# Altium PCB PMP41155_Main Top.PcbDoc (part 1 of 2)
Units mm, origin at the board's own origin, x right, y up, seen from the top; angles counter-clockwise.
Board outline 74 x 151.7 mm, 8 copper layers (Top Layer, Signal Layer 1, Signal Layer 2, Signal Layer 3, Signal Layer 4, Signal Layer 5, Signal Layer 6, Bottom Layer), stack 1.534 mm thick; 14 components, 3 nets, 47 pads, 370 vias.
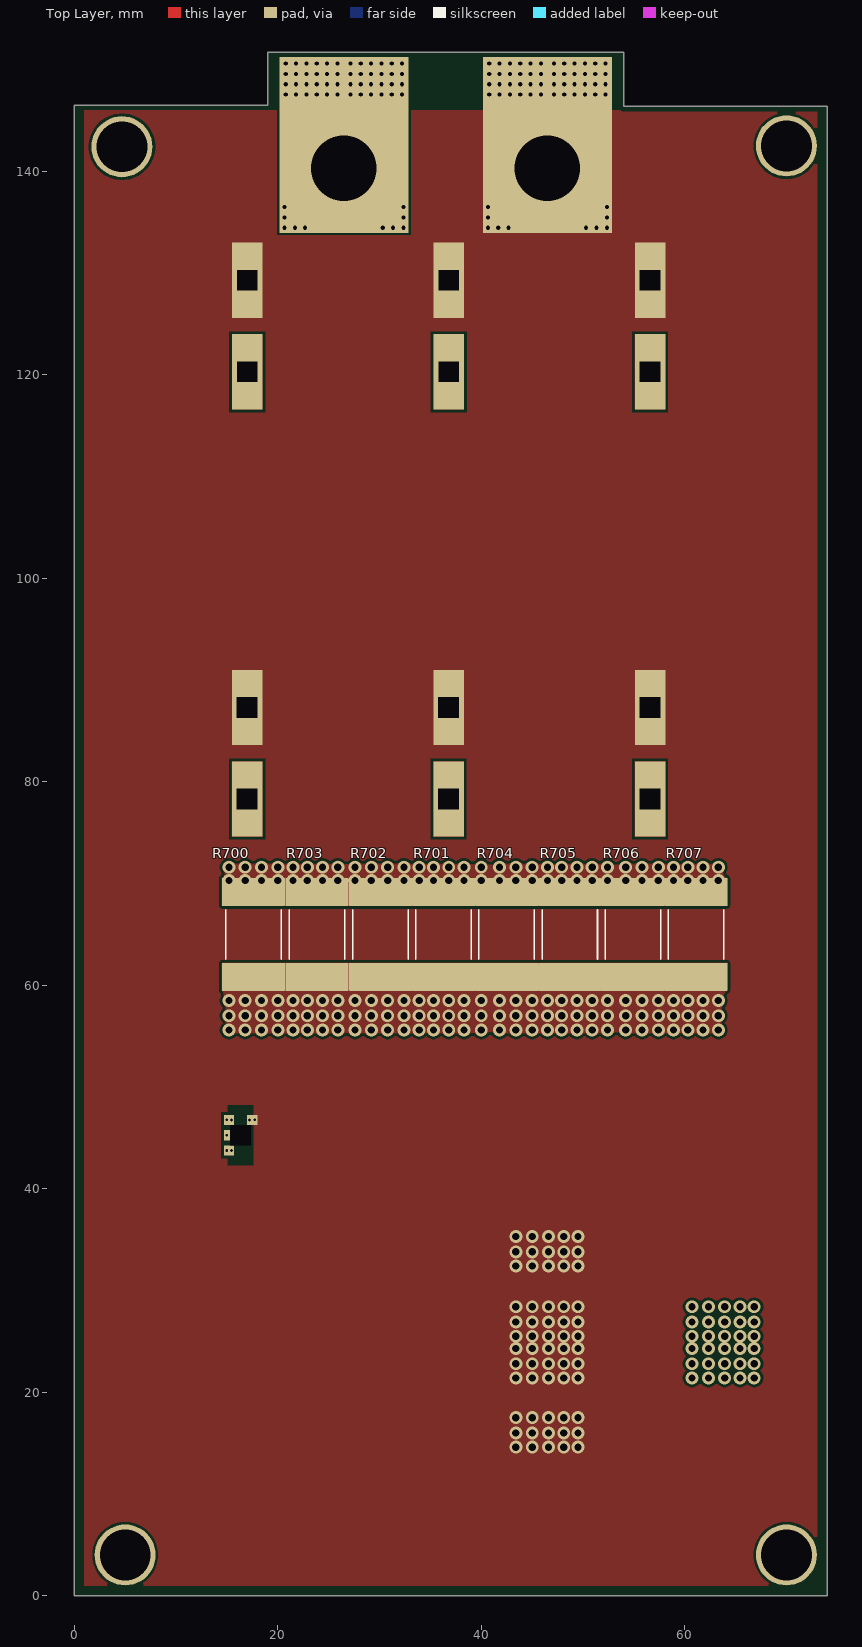
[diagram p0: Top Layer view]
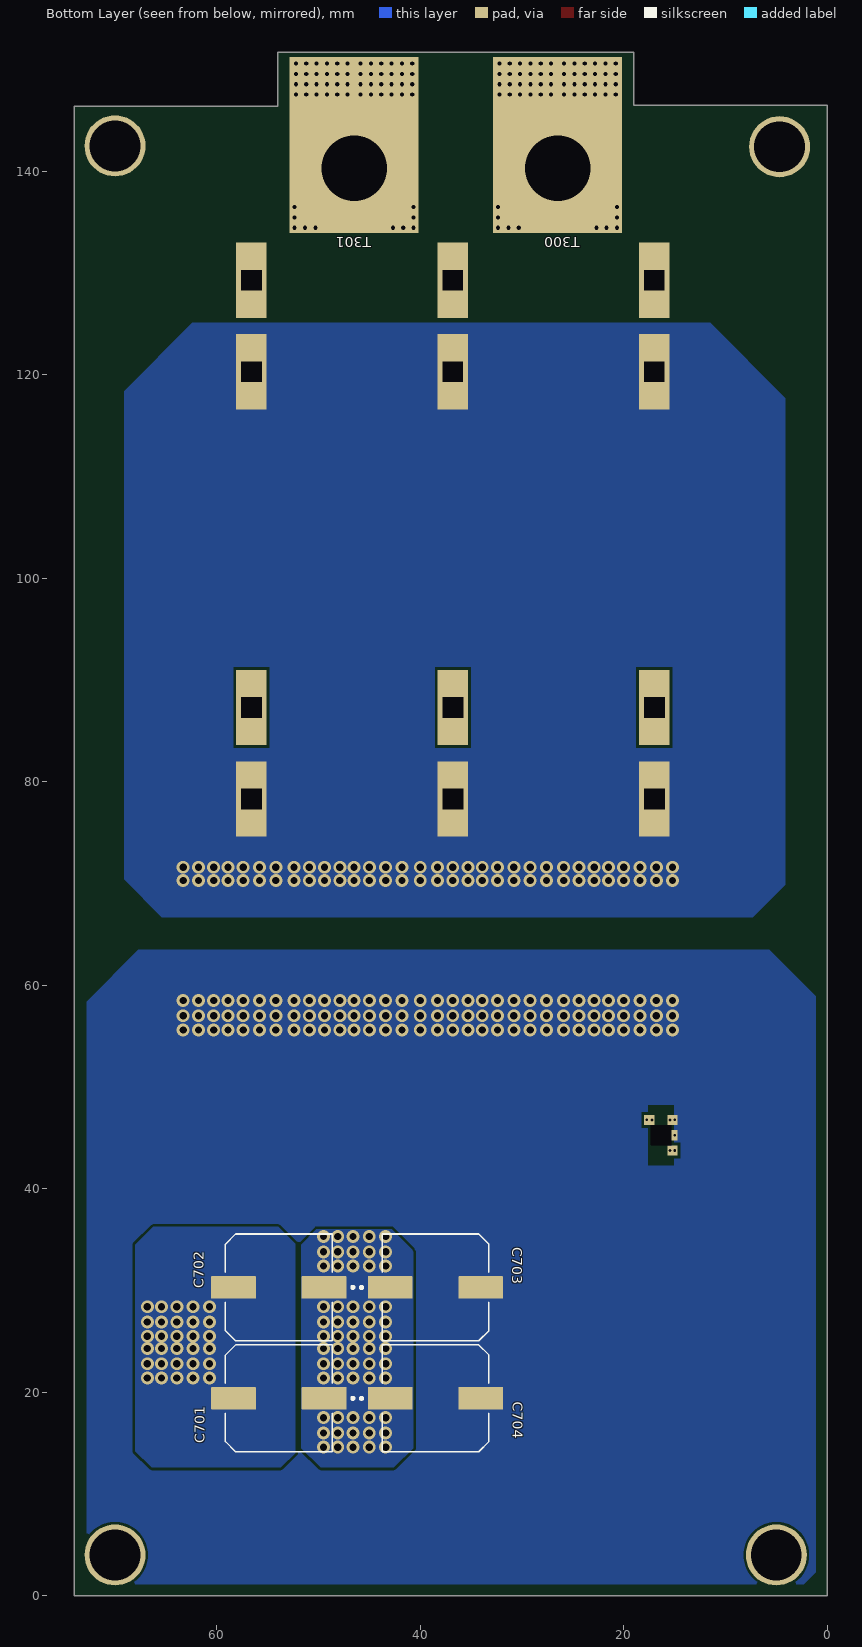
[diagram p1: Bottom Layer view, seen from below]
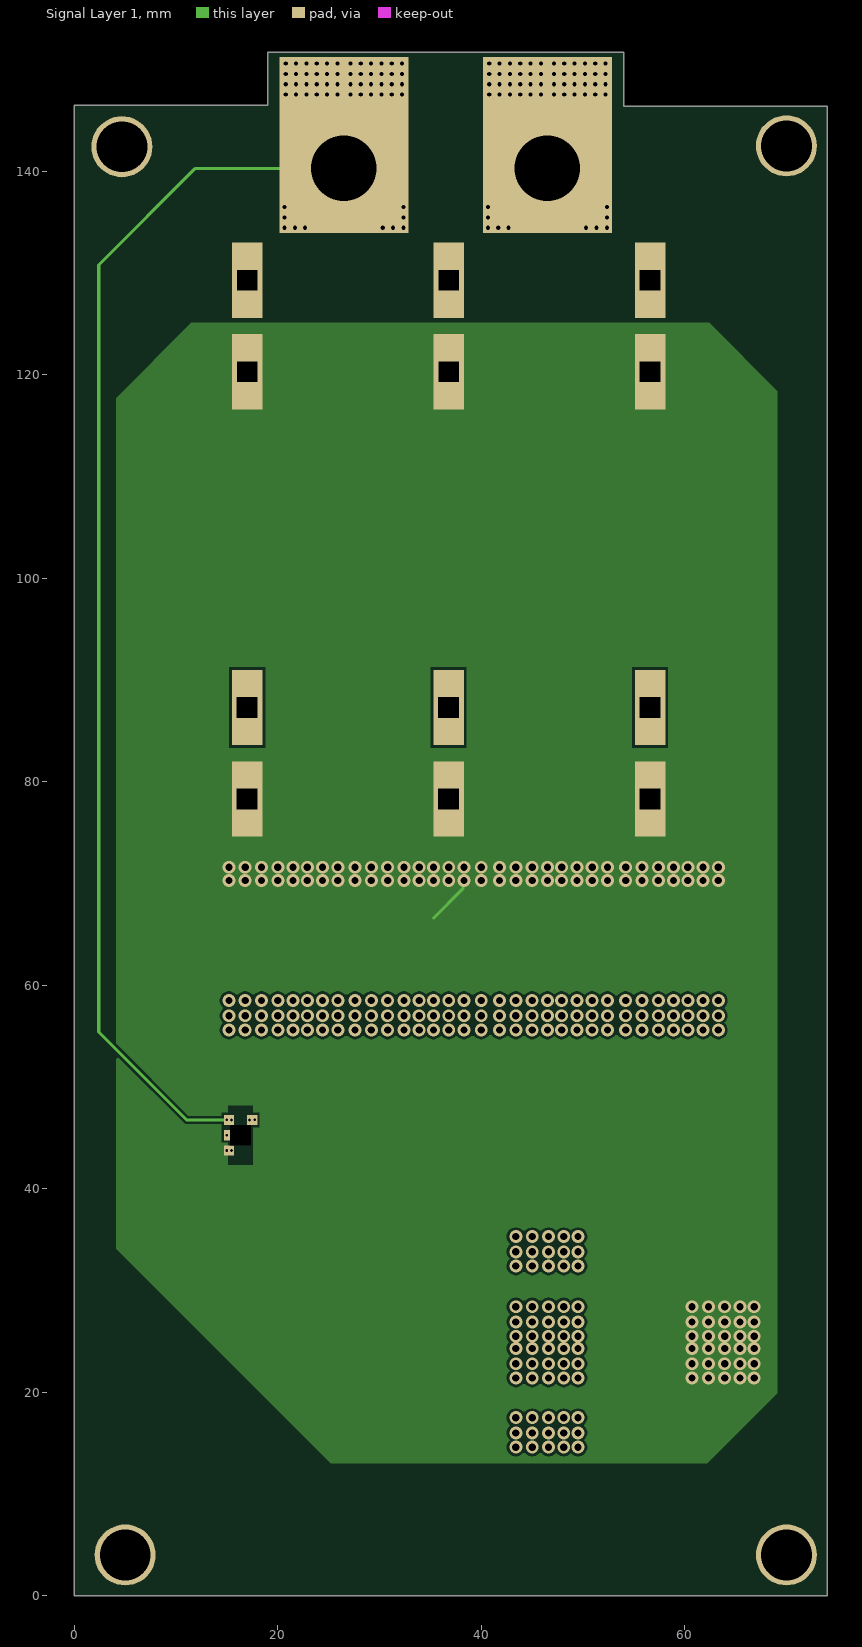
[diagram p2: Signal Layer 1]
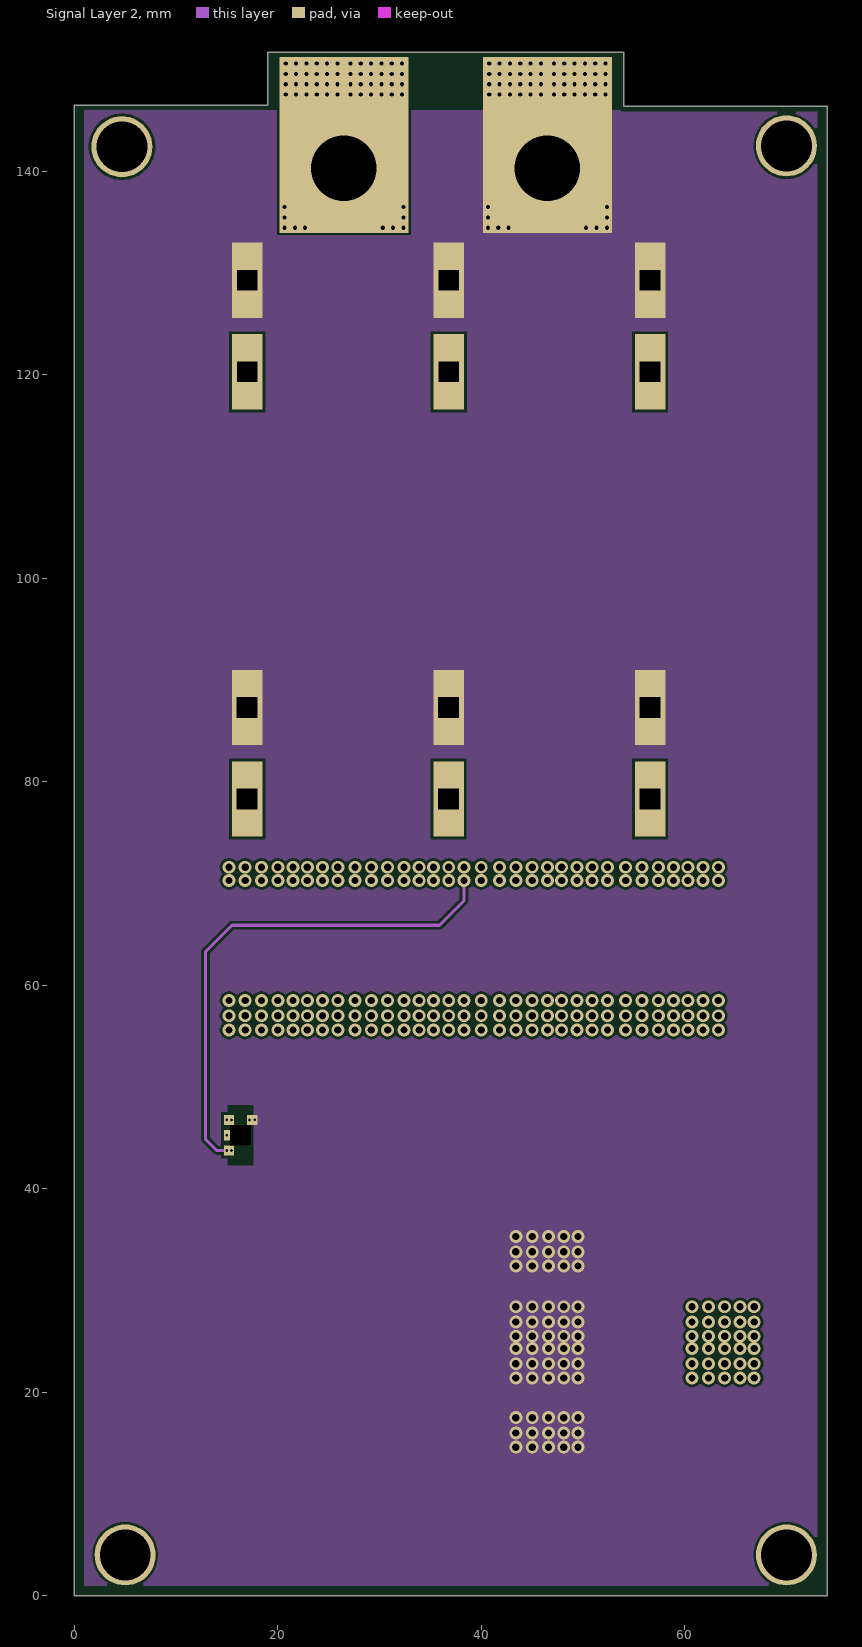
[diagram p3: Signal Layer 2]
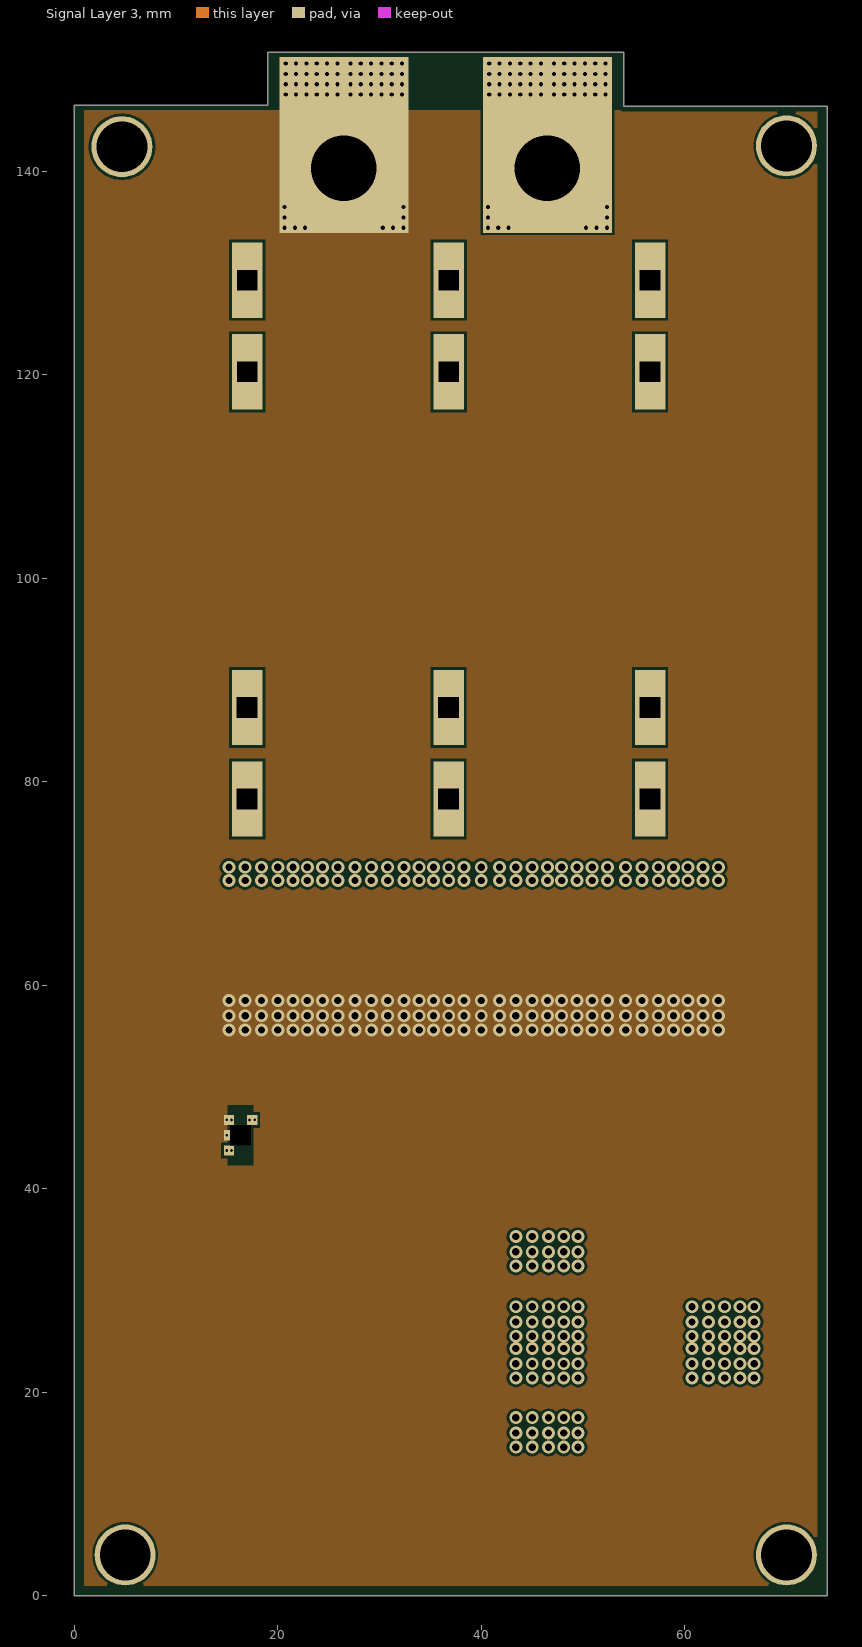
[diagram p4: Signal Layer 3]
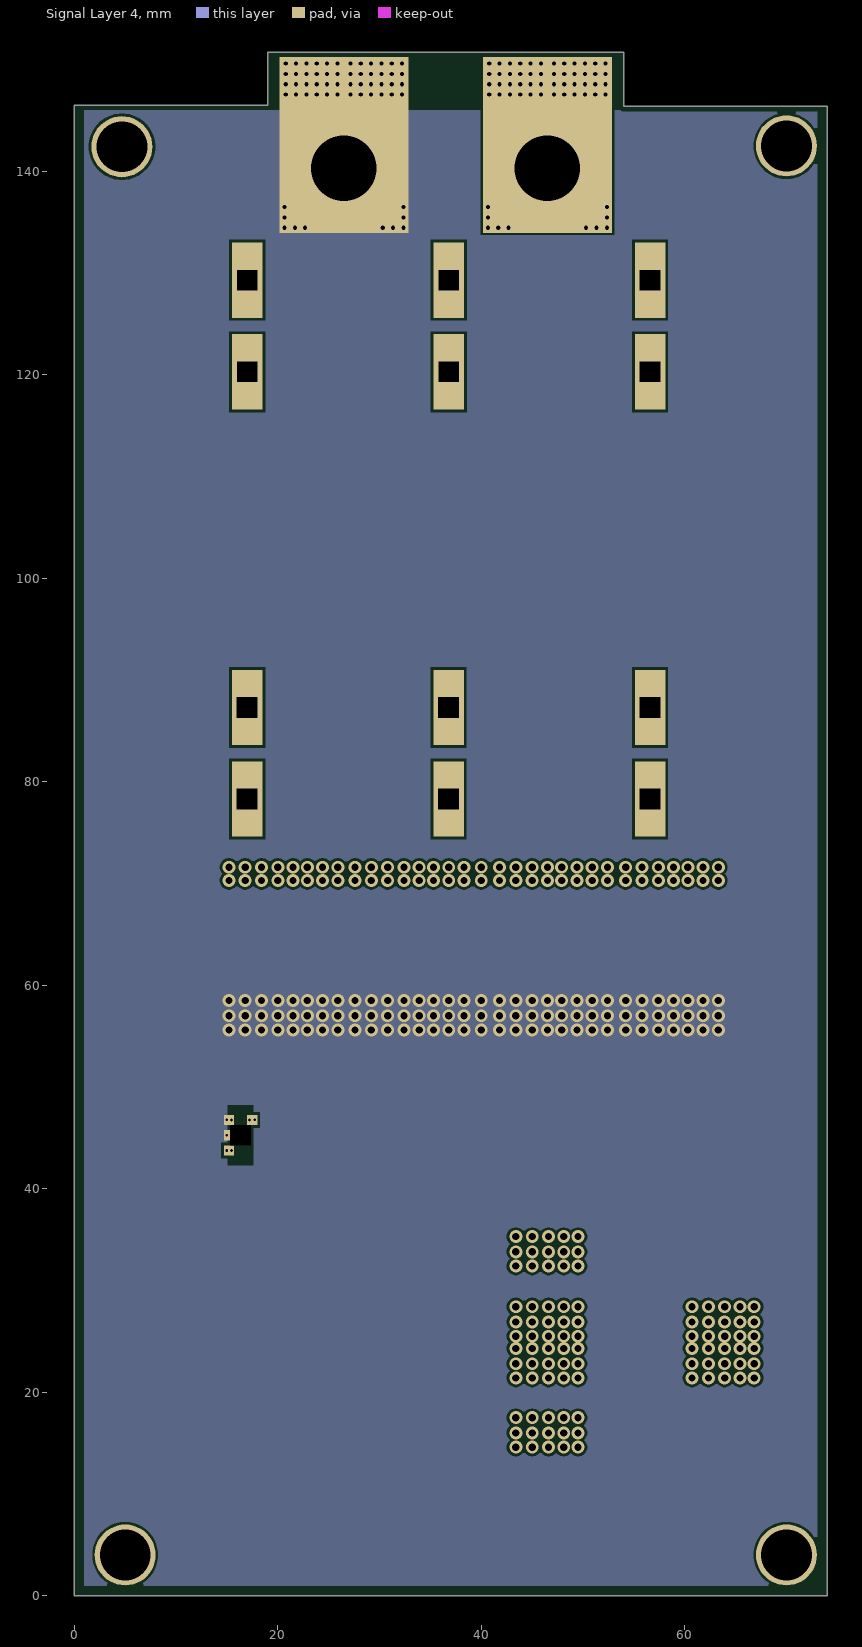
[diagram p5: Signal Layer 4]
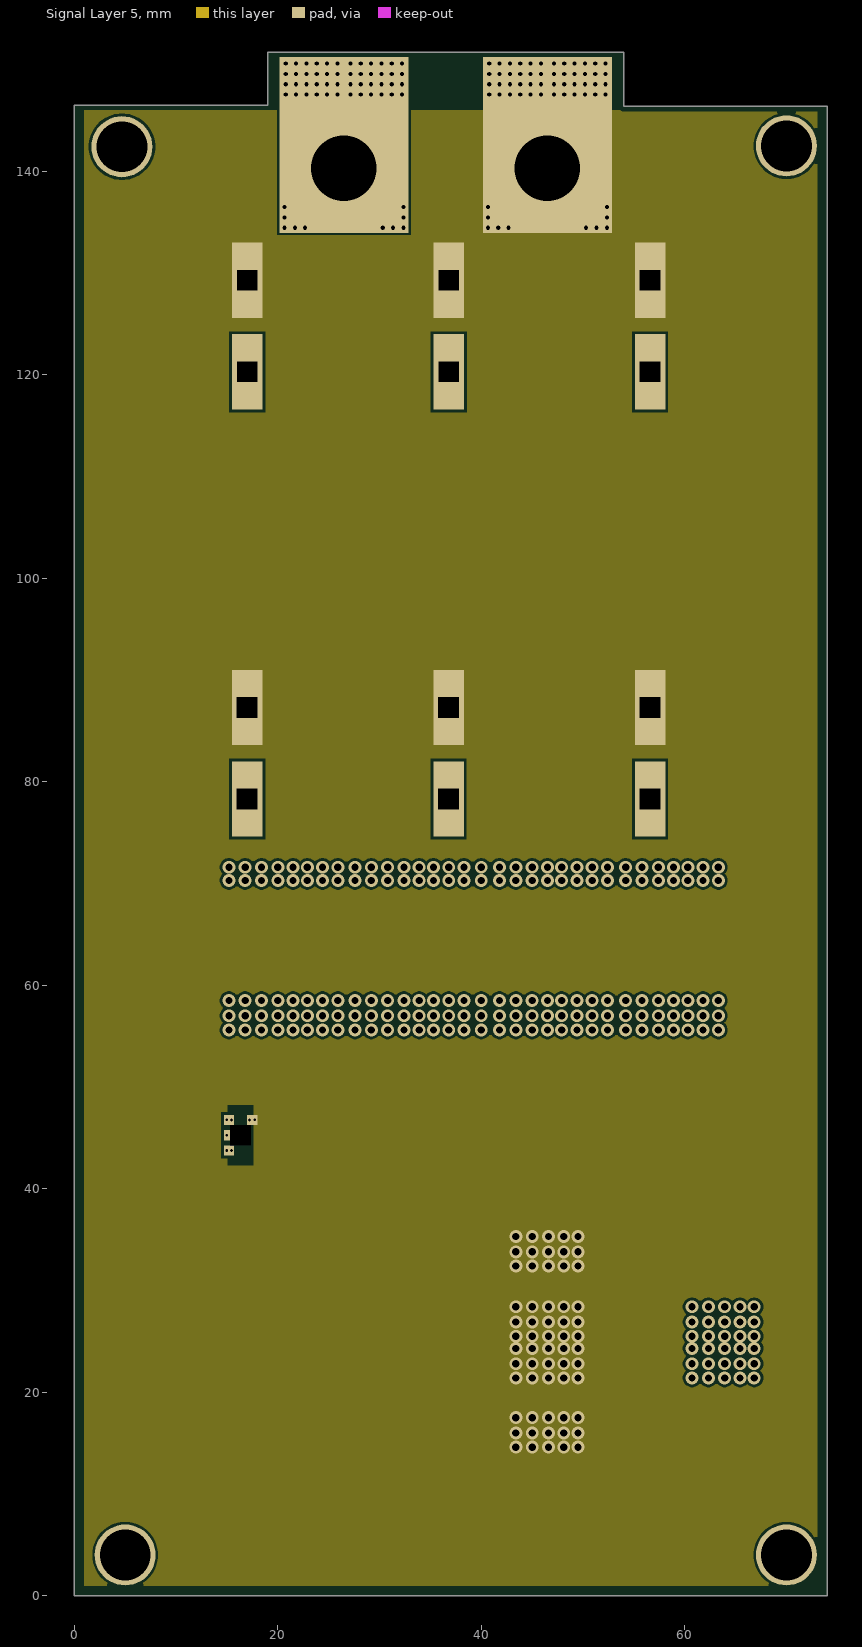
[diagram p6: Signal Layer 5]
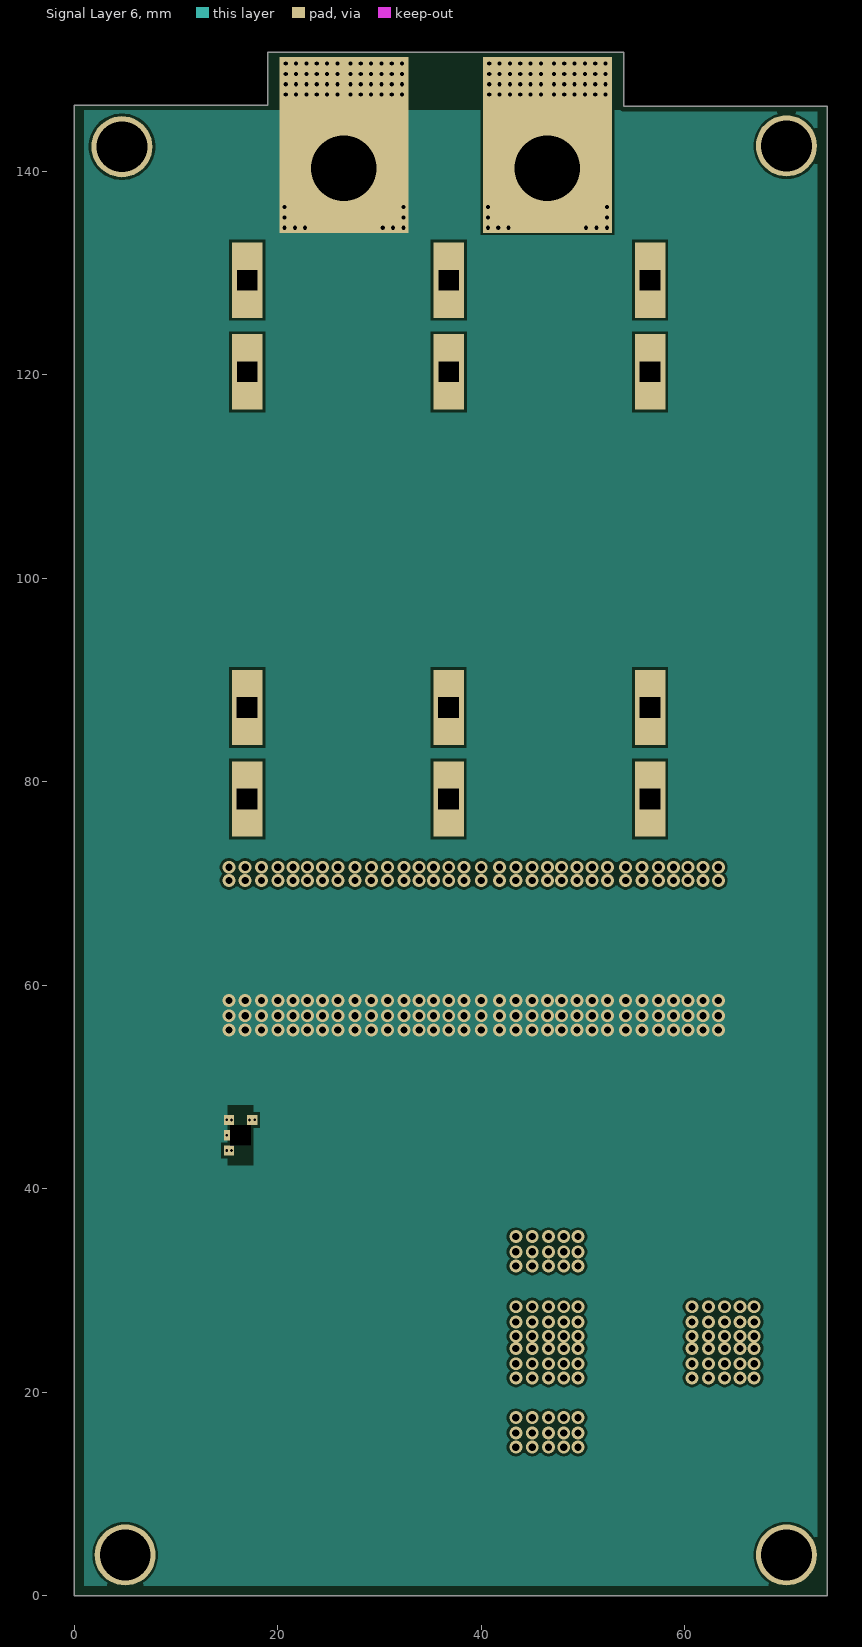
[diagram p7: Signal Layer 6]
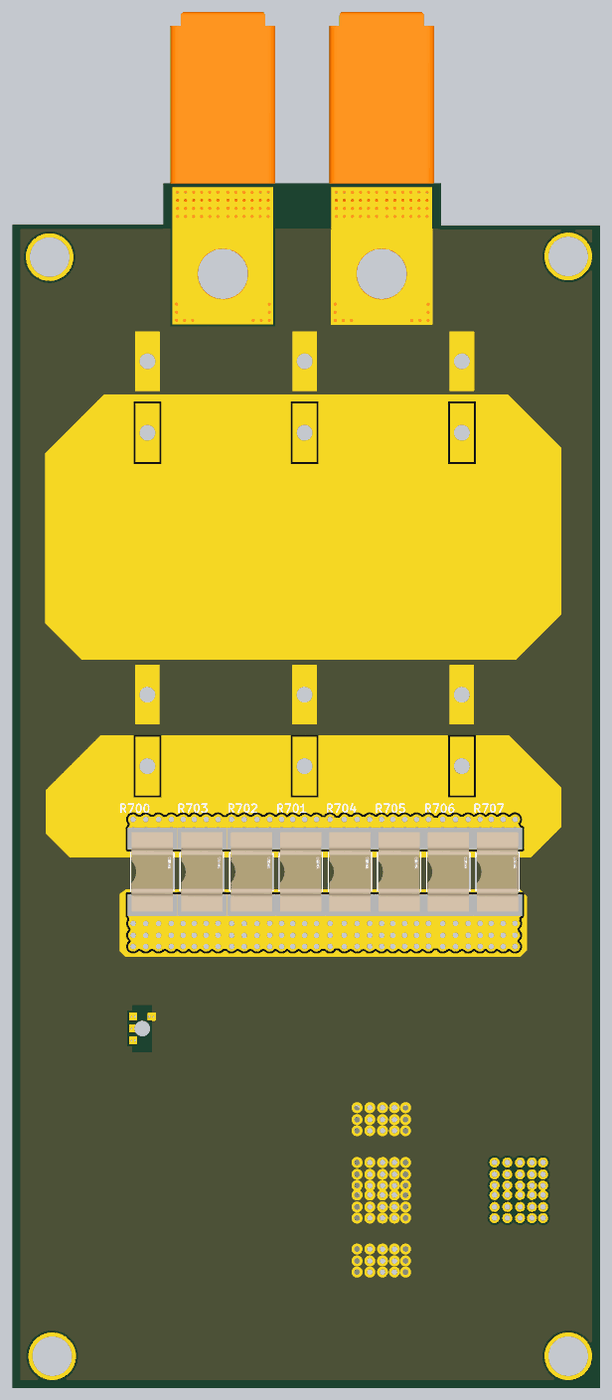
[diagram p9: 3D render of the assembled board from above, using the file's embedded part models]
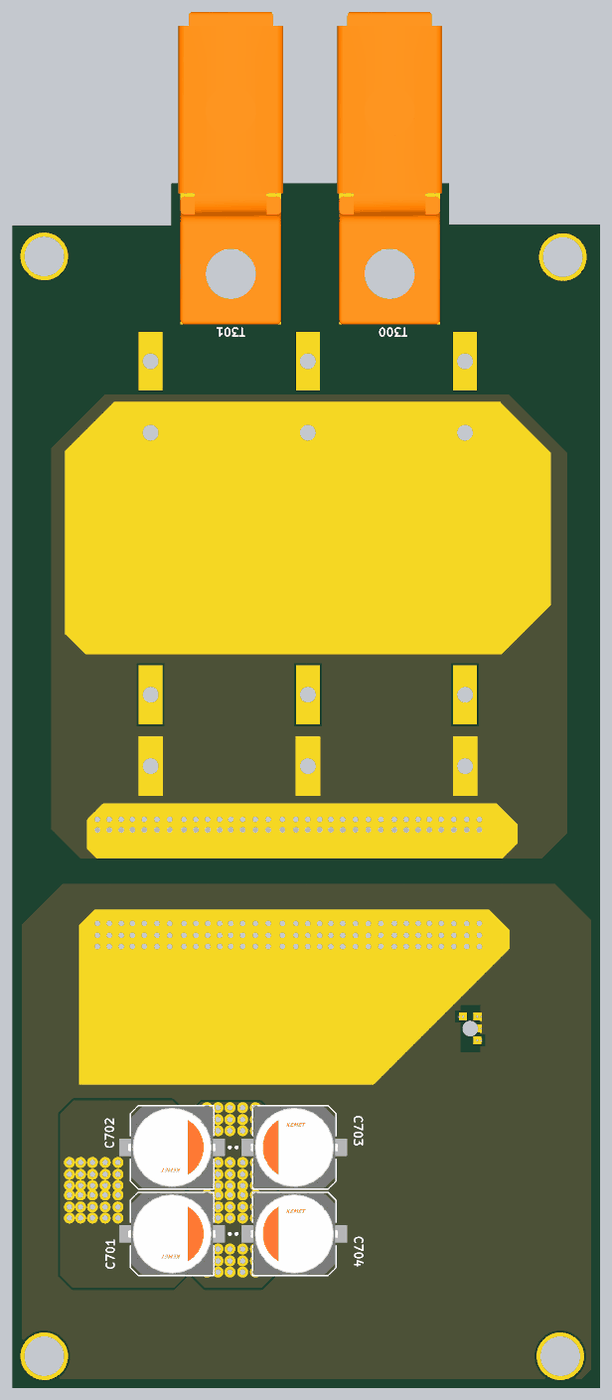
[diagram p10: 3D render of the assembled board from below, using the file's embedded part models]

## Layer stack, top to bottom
Top Solder: solder mask 0.01, Solder Resist, Dk 3.5
Top Layer: signal copper 0.0711
Dielectric1: prepreg 0.127, FR-4, Dk 4.2
Signal Layer 1: signal copper 0.0711
Dielectric 2: core 0.1524, FR-4, Dk 4.2
Signal Layer 2: signal copper 0.0711
Dielectric 3: prepreg 0.127, Dk 4.2
Signal Layer 3: signal copper 0.0711
Dielectric 4: core 0.1524, Dk 4.2
Signal Layer 4: signal copper 0.0711
Dielectric 6: prepreg 0.127, Dk 4.2
Signal Layer 5: signal copper 0.0711
Dielectric 7: core 0.1524, Dk 4.2
Signal Layer 6: signal copper 0.0711
Dielectric 5: prepreg 0.127, Dk 4.2
Bottom Layer: signal copper 0.0711
Bottom Solder: solder mask 0.01, Solder Resist, Dk 3.5

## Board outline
0,0 0,146.5 19,146.5 19,151.7 54,151.7 54,146.4 74,146.4 74,0

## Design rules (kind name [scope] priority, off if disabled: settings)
AcuteAngle [All] p1: minimum=4.50000000000000E+0001 checktracksonly=FALSE
AssemblyTestPointUsage [All] p1: valid=2
BoardOutlineClearance BoardOutlineClearance_MountingHoles [OnCopper and InComponentClass('Mounting Holes')] p1: gap=1.016 ignorepadtopadclearanceinfootprint=FALSE
BoardOutlineClearance BoardOutlineClearance_Poly [OnCopper and IsPoly] p2: gap=0.508 ignorepadtopadclearanceinfootprint=FALSE
BoardOutlineClearance [OnCopper and Not InComponentClass('Logo') and not InComponentClass('FiducialMark') and not InRegion(1000,500,4000,800) and not InPoly] p3: gap=0.254 ignorepadtopadclearanceinfootprint=FALSE
Clearance Clearance_1 [InNetClass('HV') vs Not InNetClass('HV')] p1: gap=0.508 ignorepadtopadclearanceinfootprint=FALSE
Clearance Clearance_Keepouts [((IsTrack Or IsArc) And Not InPoly) And IsFree and IsKeepOut vs ((IsTrack Or IsArc) And Not InPoly) And IsFree and IsKeepOut] p2: gap=0 ignorepadtopadclearanceinfootprint=FALSE
Clearance Clearance_Poly [InPolygon] p3: gap=0.254 ignorepadtopadclearanceinfootprint=FALSE
Clearance Clearance_FiducialMark [IsKeepOut and InComponentClass('FiducialMark') vs IsPad and InComponentClass('FiducialMark')] p4: gap=0 ignorepadtopadclearanceinfootprint=FALSE
Clearance [All] p5: gap=0.147 ignorepadtopadclearanceinfootprint=FALSE
ComponentClearance ComponentClearance_MountingHoles_FiducialMarks [InComponentClass('Mounting Holes') vs InComponentClass('FiducialMark')] p1: gap=1.27 collisioncheckmode=3 verticalgap=0.254 showdistances=FALSE
ComponentClearance ComponentClearance_Shunt [InComponentClass('Header') vs InComponentClass('Shunt')] p2: gap=0 collisioncheckmode=3 verticalgap=0 showdistances=FALSE
ComponentClearance ComponentClearance_Logo [InComponentClass('Logo')] p3: gap=1.27 collisioncheckmode=3 verticalgap=0.254 showdistances=FALSE
ComponentClearance ComponentClearance_ScrewToNut [(HasFootprint('NY PMS 440 0025 PH')) vs (HasFootprint('Keystone_1902C'))] p4: gap=0.127 collisioncheckmode=3 verticalgap=0.254 showdistances=FALSE
ComponentClearance ComponentClearance_MountingHoles [InComponentClass('Mounting Holes')] p5: gap=6.35 collisioncheckmode=3 verticalgap=2540 showdistances=FALSE
ComponentClearance ComponentClearance_SmallPassives [HasFootprint('0201*') or HasFootprint('0402*') or HasFootprint('0508') or HasFootprint('0603*') or HasFootprint('0612') or HasFootprint('0805*') or HasFootprint('0815*') or HasFootprint('0830*') or HasFootprint('1206*') or HasFootprint('1210*') or HasFootprint('1808*') or HasFootprint('1812*') or HasFootprint('1825*') or HasFootprint('2010*') or HasFootprint('2220*') or HasFootprint('2225*') or HasFootprint('2512*') or HasFootprint('2728*') or HasFootprint('3518*') vs HasFootprint('0201*') or HasFootprint('0402*') or HasFootprint('0508') or HasFootprint('0603*') or HasFootprint('0612') or HasFootprint('0805*') or HasFootprint('0815*') or HasFootprint('0830*') or HasFootprint('1206*') or HasFootprint('1210*') or HasFootprint('1808*') or HasFootprint('1812*') or HasFootprint('1825*') or HasFootprint('2010*') or HasFootprint('2220*') or HasFootprint('2225*') or HasFootprint('2512*') or HasFootprint('2728*') or HasFootprint('3518*')] p6: gap=0.254 collisioncheckmode=3 verticalgap=0.254 showdistances=FALSE
ComponentClearance ComponentClearance_THtoSMT [IsThruComponent vs IsSMTComponent] p7: gap=0.508 collisioncheckmode=3 verticalgap=0.762 showdistances=FALSE
ComponentClearance ComponentClearance_THtoTH [IsThruComponent vs IsThruComponent] p8: gap=0.508 collisioncheckmode=3 verticalgap=0.508 showdistances=FALSE
ComponentClearance [All] p9: gap=0.14 collisioncheckmode=3 verticalgap=0.14 showdistances=FALSE
DiffPairsRouting [All] p1: maxlimit=2.54 minlimit=0.254 mostfreqgap=0.254 toplayer_minwidth=0.381 toplayer_maxwidth=0.381 toplayer_prefwidth=0.381 midlayer1_minwidth=0.381 midlayer1_maxwidth=0.381 midlayer1_prefwidth=0.381 midlayer2_minwidth=0.381 midlayer2_maxwidth=0.381 midlayer2_prefwidth=0.381 midlayer3_minwidth=0.381 midlayer3_maxwidth=0.381 midlayer3_prefwidth=0.381 midlayer4_minwidth=0.381 midlayer4_maxwidth=0.381 midlayer4_prefwidth=0.381 midlayer5_minwidth=0.381 midlayer5_maxwidth=0.381 midlayer5_prefwidth=0.381 midlayer6_minwidth=0.381 midlayer6_maxwidth=0.381 midlayer6_prefwidth=0.381 bottomlayer_minwidth=0.381 bottomlayer_maxwidth=0.381 bottomlayer_prefwidth=0.381 maxuncoupledlength=25.4
FabricationTestPointUsage TestPointUsage [All] p1: valid=2 allowmultiple=FALSE
FabricationTestpoint Testpoint [All] p1: side=3 testpointundercomponent=TRUE minsize=1.016 maxsize=2.54 preferedsize=1.524 minholesize=0 maxholesize=1.016 preferedholesize=0.813 testpointgrid=0.025 allowsidetop=TRUE allowsidebottom=TRUE usegrid=TRUE gridtolerance=0
FanoutControl Fanout_LCC [IsLCC] p1: bgadir=Out bgaviamode=Centered fanoutstyle=Auto fanoutdirection=Alternating viagrid=0.025 // Fanout_LCC (Default Rule)
FanoutControl Fanout_BGA [IsBGA] p2: bgadir=Out bgaviamode=Centered fanoutstyle=Auto fanoutdirection=Alternating viagrid=0.025 // Fanout_BGA (Default Rule)
FanoutControl Fanout_Default [All] p4: bgadir=Out bgaviamode=Centered fanoutstyle=Auto fanoutdirection=Alternating viagrid=0.025 // Fanout_Default (Default Rule)
FanoutControl Fanout_Small [(CompPinCount < 5)] p5: bgadir=Out bgaviamode=Centered fanoutstyle=Auto fanoutdirection=OutThenIn viagrid=0.025 // Fanout_Small (Default Rule)
HoleSize [All] p1: absolutevalues=TRUE maxlimit=6.604 minlimit=0.2 maxpercent=80.000 minpercent=20.000
MinimumAnnularRing MinimumAnnularRing_ThermalPadVias [IsVia and InAnyComponent] p1: minimumring=0.15
MinimumAnnularRing [All] p2: minimumring=0.127
MinimumSolderMaskSliver MinimumSolderMaskSliver_Logo [InComponentClass('Logo') vs InComponentClass('Logo')] p1: minsoldermaskwidth=0.018
MinimumSolderMaskSliver [All] p2: minsoldermaskwidth=0.076
PlaneClearance [All] p1: clearance=0
PlaneConnect [All] p1: planeconnectstyle=Direct reliefexpansion=0.254 reliefentries=4 reliefconductorwidth=0.254 reliefairgap=0
PolygonConnect PolygonConnect_32 [All vs IsNamedPolygon('5V') Or  IsNamedPolygon('CS-_total_charge_current_battery') Or  IsNamedPolygon('5V') Or  IsNamedPolygon('CS-_total_charge_current_battery') Or  IsNamedPolygon('48Vout2') Or  IsNamedPolygon('48VOUT1') Or  IsNamedPolygon('SGND') Or  IsNamedPolygon('48Vout2') Or  IsNamedPolygon('CS-_total_discharge_current_bus') Or  IsNamedPolygon('5V') Or  IsNamedPolygon('48Vout2') Or  IsNamedPolygon('5V') Or  IsNamedPolygon('5V') Or  IsNamedPolygon('VBAT-') Or  IsNamedPolygon('5V') Or  IsNamedPolygon('48Vout2') Or  IsNamedPolygon('VBAT-') Or  IsNamedPolygon('48Vout2') Or  IsNamedPolygon('5V') Or  IsNamedPolygon('5V') Or  IsNamedPolygon('48Vout2') Or  IsNamedPolygon('5V') Or  IsNamedPolygon('CS-_total_charge_current_battery') Or  IsNamedPolygon('SGND') Or  IsNamedPolygon('SGND') Or  IsNamedPolygon('SGND') Or  IsNamedPolygon('CS-_total_discharge_current_bus') Or  IsNamedPolygon('SGND') Or  IsNamedPolygon('SGND') Or  IsNamedPolygon('CS-_total_charge_current_battery') Or  IsNamedPolygon('SGND') Or  IsNamedPolygon('48Vout1') Or  IsNamedPolygon('SGND') Or  IsNamedPolygon('CS-_total_charge_current_battery') Or  IsNamedPolygon('SGND') Or  IsNamedPolygon('VBAT-') Or  IsNamedPolygon('CS-_total_discharge_current_bus') Or  IsNamedPolygon('VBAT-') Or  IsNamedPolygon('VBAT-') Or  IsNamedPolygon('VBAT-') Or  IsNamedPolygon('CS-_total_discharge_current_bus') Or  IsNamedPolygon('SGND') Or  IsNamedPolygon('48Vout2') Or  IsNamedPolygon('VBAT-') Or  IsNamedPolygon('48Vout2') Or  IsNamedPolygon('VBAT-') Or  IsNamedPolygon('CS-') Or  IsNamedPolygon('SGND') Or  IsNamedPolygon('VBAT-') Or  IsNamedPolygon('SGND') Or  IsNamedPolygon('VBAT-') Or  IsNamedPolygon('48Vout1') Or  IsNamedPolygon('VBAT-') Or  IsNamedPolygon('CS-') Or  IsNamedPolygon('SGND') Or  IsNamedPolygon('48Vout1') Or  IsNamedPolygon('SGND') Or  IsNamedPolygon('VBAT-') Or  IsNamedPolygon('SGND') Or  IsNamedPolygon('CS-_total_charge_current_battery') Or  IsNamedPolygon('CS-_total_charge_current_battery') Or  IsNamedPolygon('VBAT-') Or  IsNamedPolygon('CS-_total_discharge_current_bus') Or  IsNamedPolygon('SGND') Or  IsNamedPolygon('CS-_total_charge_current_battery') Or  IsNamedPolygon('CS+_total_charge_current_battery') Or  IsNamedPolygon('48Vout1') Or  IsNamedPolygon('VBAT-') Or  IsNamedPolygon('SGND') Or  IsNamedPolygon('CS-_total_discharge_current_bus') Or  IsNamedPolygon('CS-_total_discharge_current_bus') Or  IsNamedPolygon('48Vout1') Or  IsNamedPolygon('SGND') Or  IsNamedPolygon('SGND') Or  IsNamedPolygon('CS-_total_charge_current_battery') Or  IsNamedPolygon('SGND') Or  IsNamedPolygon('VBAT-') Or  IsNamedPolygon('SGND') Or  IsNamedPolygon('SGND') Or  IsNamedPolygon('SGND') Or  IsNamedPolygon('VBAT-') Or  IsNamedPolygon('48Vout2') Or  IsNamedPolygon('VBAT-') Or  IsNamedPolygon('CS-_total_charge_current_battery') Or  IsNamedPolygon('CS-_total_charge_current_battery') Or  IsNamedPolygon('48Vout1') Or  IsNamedPolygon('SGND') Or  IsNamedPolygon('SGND') Or  IsNamedPolygon('CS+_total_charge_current_battery') Or  IsNamedPolygon('CS-_total_discharge_current_bus') Or  IsNamedPolygon('SGND') Or  IsNamedPolygon('48Vout1') Or  IsNamedPolygon('CS-_total_discharge_current_bus') Or  IsNamedPolygon('48V2') Or  IsNamedPolygon('CS-')] p1: connectstyle=Direct reliefconductorwidth=0.254 reliefentries=4 polygonreliefangle="90 Angle" airgapwidth=0.254
PolygonConnect PolygonConnect_31 [All vs IsNamedPolygon('CS-_total_charge_current_battery') Or  IsNamedPolygon('5V') Or  IsNamedPolygon('5V') Or  IsNamedPolygon('48Vout2') Or  IsNamedPolygon('CS-_total_discharge_current_bus') Or  IsNamedPolygon('5V') Or  IsNamedPolygon('VBAT-') Or  IsNamedPolygon('48Vout2') Or  IsNamedPolygon('5V') Or  IsNamedPolygon('5V') Or  IsNamedPolygon('CS-_total_charge_current_battery') Or  IsNamedPolygon('48Vout2') Or  IsNamedPolygon('VBAT-') Or  IsNamedPolygon('5V') Or  IsNamedPolygon('48Vout2') Or  IsNamedPolygon('5V') Or  IsNamedPolygon('48Vout2') Or  IsNamedPolygon('48Vout2') Or  IsNamedPolygon('VBAT-') Or  IsNamedPolygon('VBAT-') Or  IsNamedPolygon('VBAT-') Or  IsNamedPolygon('48Vout1') Or  IsNamedPolygon('VBAT-') Or  IsNamedPolygon('48Vout1') Or  IsNamedPolygon('48Vout1') Or  IsNamedPolygon('VBAT-') Or  IsNamedPolygon('CS-_total_charge_current_battery') Or  IsNamedPolygon('CS-_total_discharge_current_bus') Or  IsNamedPolygon('CS-') Or  IsNamedPolygon('48Vout2') Or  IsNamedPolygon('CS-_total_charge_current_battery') Or  IsNamedPolygon('VBAT-') Or  IsNamedPolygon('CS+_total_charge_current_battery') Or  IsNamedPolygon('VBAT-') Or  IsNamedPolygon('CS-_total_charge_current_battery') Or  IsNamedPolygon('VBAT-') Or  IsNamedPolygon('48Vout2') Or  IsNamedPolygon('VBAT-') Or  IsNamedPolygon('VBAT-') Or  IsNamedPolygon('CS-') Or  IsNamedPolygon('CS-_total_discharge_current_bus') Or  IsNamedPolygon('CS-_total_discharge_current_bus') Or  IsNamedPolygon('CS-_total_charge_current_battery') Or  IsNamedPolygon('VBAT-') Or  IsNamedPolygon('VBAT-') Or  IsNamedPolygon('VBAT-') Or  IsNamedPolygon('VBAT-') Or  IsNamedPolygon('VBAT-') Or  IsNamedPolygon('VBAT-') Or  IsNamedPolygon('VBAT-') Or  IsNamedPolygon('CS-_total_charge_current_battery') Or  IsNamedPolygon('VBAT-') Or  IsNamedPolygon('VBAT-') Or  IsNamedPolygon('VBAT-') Or  IsNamedPolygon('VBAT-') Or  IsNamedPolygon('CS-_total_discharge_current_bus') Or  IsNamedPolygon('48V2') Or  IsNamedPolygon('5V') Or  IsNamedPolygon('CS-_total_discharge_current_bus') Or  IsNamedPolygon('48Vout1') Or  IsNamedPolygon('48Vout1') Or  IsNamedPolygon('VBAT-') Or  IsNamedPolygon('VBAT-') Or  IsNamedPolygon('CS-_total_charge_current_battery') Or  IsNamedPolygon('VBAT-') Or  IsNamedPolygon('VBAT-') Or  IsNamedPolygon('CS-_total_discharge_current_bus') Or  IsNamedPolygon('VBAT-') Or  IsNamedPolygon('VBAT-') Or  IsNamedPolygon('CS-_total_discharge_current_bus') Or  IsNamedPolygon('CS-') Or  IsNamedPolygon('48VOUT1') Or  IsNamedPolygon('VBAT-') Or  IsNamedPolygon('48Vout1') Or  IsNamedPolygon('5V') Or  IsNamedPolygon('48Vout1') Or  IsNamedPolygon('VBAT-') Or  IsNamedPolygon('VBAT-') Or  IsNamedPolygon('CS-_total_charge_current_battery') Or  IsNamedPolygon('VBAT-') Or  IsNamedPolygon('VBAT-') Or  IsNamedPolygon('VBAT-') Or  IsNamedPolygon('VBAT-') Or  IsNamedPolygon('VBAT-') Or  IsNamedPolygon('CS+_total_charge_current_battery') Or  IsNamedPolygon('VBAT-')] p2: connectstyle=Direct reliefconductorwidth=0.254 reliefentries=4 polygonreliefangle="90 Angle" airgapwidth=0.254
PolygonConnect PolygonConnect_30 [All vs IsNamedPolygon('48Vout2') Or  IsNamedPolygon('VBAT-') Or  IsNamedPolygon('VBAT-') Or  IsNamedPolygon('CS-_total_charge_current_battery') Or  IsNamedPolygon('48Vout1') Or  IsNamedPolygon('5V') Or  IsNamedPolygon('VBAT-') Or  IsNamedPolygon('48Vout2') Or  IsNamedPolygon('VBAT-') Or  IsNamedPolygon('CS-_total_discharge_current_bus') Or  IsNamedPolygon('CS+_total_charge_current_battery') Or  IsNamedPolygon('VBAT-') Or  IsNamedPolygon('CS-_total_charge_current_battery') Or  IsNamedPolygon('48VOUT1') Or  IsNamedPolygon('VBAT-') Or  IsNamedPolygon('VBAT-') Or  IsNamedPolygon('CS-_total_discharge_current_bus') Or  IsNamedPolygon('VBAT-') Or  IsNamedPolygon('5V') Or  IsNamedPolygon('48Vout2') Or  IsNamedPolygon('CS-_total_charge_current_battery') Or  IsNamedPolygon('VBAT-') Or  IsNamedPolygon('5V') Or  IsNamedPolygon('VBAT-') Or  IsNamedPolygon('5V') Or  IsNamedPolygon('VBAT-') Or  IsNamedPolygon('CS-_total_discharge_current_bus') Or  IsNamedPolygon('VBAT-') Or  IsNamedPolygon('48Vout1') Or  IsNamedPolygon('CS-_total_discharge_current_bus') Or  IsNamedPolygon('VBAT-') Or  IsNamedPolygon('5V') Or  IsNamedPolygon('48Vout2') Or  IsNamedPolygon('CS-') Or  IsNamedPolygon('VBAT-') Or  IsNamedPolygon('CS+_total_charge_current_battery') Or  IsNamedPolygon('VBAT-') Or  IsNamedPolygon('VBAT-') Or  IsNamedPolygon('CS-_total_charge_current_battery') Or  IsNamedPolygon('48Vout2') Or  IsNamedPolygon('VBAT-') Or  IsNamedPolygon('CS-_total_charge_current_battery') Or  IsNamedPolygon('48Vout1') Or  IsNamedPolygon('CS-_total_charge_current_battery') Or  IsNamedPolygon('48Vout2') Or  IsNamedPolygon('VBAT-') Or  IsNamedPolygon('VBAT-') Or  IsNamedPolygon('VBAT-') Or  IsNamedPolygon('VBAT-') Or  IsNamedPolygon('CS-') Or  IsNamedPolygon('48Vout1') Or  IsNamedPolygon('CS-') Or  IsNamedPolygon('CS-_total_charge_current_battery') Or  IsNamedPolygon('VBAT-') Or  IsNamedPolygon('VBAT-') Or  IsNamedPolygon('48Vout1') Or  IsNamedPolygon('CS-_total_discharge_current_bus') Or  IsNamedPolygon('VBAT-') Or  IsNamedPolygon('VBAT-') Or  IsNamedPolygon('VBAT-') Or  IsNamedPolygon('CS-_total_discharge_current_bus') Or  IsNamedPolygon('5V') Or  IsNamedPolygon('48Vout2') Or  IsNamedPolygon('VBAT-') Or  IsNamedPolygon('VBAT-') Or  IsNamedPolygon('VBAT-') Or  IsNamedPolygon('48Vout1') Or  IsNamedPolygon('VBAT-') Or  IsNamedPolygon('5V') Or  IsNamedPolygon('VBAT-') Or  IsNamedPolygon('VBAT-') Or  IsNamedPolygon('VBAT-') Or  IsNamedPolygon('5V') Or  IsNamedPolygon('48V2') Or  IsNamedPolygon('CS-_total_discharge_current_bus') Or  IsNamedPolygon('VBAT-') Or  IsNamedPolygon('VBAT-') Or  IsNamedPolygon('CS-_total_charge_current_battery') Or  IsNamedPolygon('48Vout1') Or  IsNamedPolygon('VBAT-') Or  IsNamedPolygon('CS-_total_charge_current_battery') Or  IsNamedPolygon('5V')] p3: connectstyle=Direct reliefconductorwidth=0.254 reliefentries=4 polygonreliefangle="90 Angle" airgapwidth=0.254
PolygonConnect PolygonConnect_29 [All vs IsNamedPolygon('CS-_total_charge_current_battery') Or  IsNamedPolygon('CS-_total_discharge_current_bus') Or  IsNamedPolygon('5V') Or  IsNamedPolygon('48Vout1') Or  IsNamedPolygon('VBAT-') Or  IsNamedPolygon('5V') Or  IsNamedPolygon('VBAT-') Or  IsNamedPolygon('48Vout2') Or  IsNamedPolygon('VBAT-') Or  IsNamedPolygon('48Vout2') Or  IsNamedPolygon('CS-_total_charge_current_battery') Or  IsNamedPolygon('VBAT-') Or  IsNamedPolygon('48Vout1') Or  IsNamedPolygon('48Vout1') Or  IsNamedPolygon('48Vout1') Or  IsNamedPolygon('VBAT-') Or  IsNamedPolygon('48VOUT1') Or  IsNamedPolygon('5V') Or  IsNamedPolygon('CS-_total_discharge_current_bus') Or  IsNamedPolygon('5V') Or  IsNamedPolygon('VBAT-') Or  IsNamedPolygon('VBAT-') Or  IsNamedPolygon('5V') Or  IsNamedPolygon('VBAT-') Or  IsNamedPolygon('VBAT-') Or  IsNamedPolygon('VBAT-') Or  IsNamedPolygon('CS-') Or  IsNamedPolygon('5V') Or  IsNamedPolygon('VBAT-') Or  IsNamedPolygon('5V') Or  IsNamedPolygon('VBAT-') Or  IsNamedPolygon('48Vout1') Or  IsNamedPolygon('CS+_total_charge_current_battery') Or  IsNamedPolygon('VBAT-') Or  IsNamedPolygon('VBAT-') Or  IsNamedPolygon('CS-_total_charge_current_battery') Or  IsNamedPolygon('5V') Or  IsNamedPolygon('VBAT-') Or  IsNamedPolygon('48Vout1') Or  IsNamedPolygon('CS-_total_charge_current_battery') Or  IsNamedPolygon('VBAT-') Or  IsNamedPolygon('CS-') Or  IsNamedPolygon('5V') Or  IsNamedPolygon('48Vout2') Or  IsNamedPolygon('CS-_total_charge_current_battery') Or  IsNamedPolygon('VBAT-') Or  IsNamedPolygon('48Vout2') Or  IsNamedPolygon('VBAT-') Or  IsNamedPolygon('48Vout2') Or  IsNamedPolygon('CS-') Or  IsNamedPolygon('VBAT-') Or  IsNamedPolygon('VBAT-') Or  IsNamedPolygon('48V2') Or  IsNamedPolygon('CS+_total_charge_current_battery') Or  IsNamedPolygon('VBAT-') Or  IsNamedPolygon('VBAT-') Or  IsNamedPolygon('VBAT-') Or  IsNamedPolygon('CS-_total_charge_current_battery') Or  IsNamedPolygon('CS-_total_discharge_current_bus') Or  IsNamedPolygon('48Vout2') Or  IsNamedPolygon('CS-_total_discharge_current_bus') Or  IsNamedPolygon('CS-_total_discharge_current_bus') Or  IsNamedPolygon('VBAT-') Or  IsNamedPolygon('48Vout1') Or  IsNamedPolygon('CS-_total_charge_current_battery') Or  IsNamedPolygon('VBAT-') Or  IsNamedPolygon('CS-_total_charge_current_battery') Or  IsNamedPolygon('CS-_total_discharge_current_bus') Or  IsNamedPolygon('VBAT-') Or  IsNamedPolygon('VBAT-') Or  IsNamedPolygon('CS-_total_charge_current_battery') Or  IsNamedPolygon('48Vout2') Or  IsNamedPolygon('CS-_total_discharge_current_bus') Or  IsNamedPolygon('VBAT-')] p4: connectstyle=Direct reliefconductorwidth=0.254 reliefentries=4 polygonreliefangle="90 Angle" airgapwidth=0.254
PolygonConnect PolygonConnect_28 [All vs IsNamedPolygon('48VOUT1') Or  IsNamedPolygon('VBAT-') Or  IsNamedPolygon('VBAT-') Or  IsNamedPolygon('VBAT-') Or  IsNamedPolygon('VBAT-') Or  IsNamedPolygon('5V') Or  IsNamedPolygon('VBAT-') Or  IsNamedPolygon('VBAT-') Or  IsNamedPolygon('VBAT-') Or  IsNamedPolygon('48Vout1') Or  IsNamedPolygon('CS-_total_discharge_current_bus') Or  IsNamedPolygon('VBAT-') Or  IsNamedPolygon('VBAT-') Or  IsNamedPolygon('CS-') Or  IsNamedPolygon('VBAT-') Or  IsNamedPolygon('CS-_total_discharge_current_bus') Or  IsNamedPolygon('CS-_total_charge_current_battery') Or  IsNamedPolygon('48Vout2') Or  IsNamedPolygon('CS-_total_charge_current_battery') Or  IsNamedPolygon('VBAT-') Or  IsNamedPolygon('CS+_total_charge_current_battery') Or  IsNamedPolygon('48Vout1') Or  IsNamedPolygon('VBAT-') Or  IsNamedPolygon('CS-_total_charge_current_battery') Or  IsNamedPolygon('5V') Or  IsNamedPolygon('48Vout2') Or  IsNamedPolygon('CS-_total_discharge_current_bus') Or  IsNamedPolygon('5V') Or  IsNamedPolygon('VBAT-') Or  IsNamedPolygon('CS-_total_charge_current_battery') Or  IsNamedPolygon('VBAT-') Or  IsNamedPolygon('VBAT-') Or  IsNamedPolygon('48Vout2') Or  IsNamedPolygon('5V') Or  IsNamedPolygon('VBAT-') Or  IsNamedPolygon('5V') Or  IsNamedPolygon('CS-_total_discharge_current_bus') Or  IsNamedPolygon('VBAT-') Or  IsNamedPolygon('CS+_total_charge_current_battery') Or  IsNamedPolygon('VBAT-') Or  IsNamedPolygon('48Vout1') Or  IsNamedPolygon('VBAT-') Or  IsNamedPolygon('CS-_total_discharge_current_bus') Or  IsNamedPolygon('CS-_total_discharge_current_bus') Or  IsNamedPolygon('CS-_total_charge_current_battery') Or  IsNamedPolygon('VBAT-') Or  IsNamedPolygon('VBAT-') Or  IsNamedPolygon('VBAT-') Or  IsNamedPolygon('CS-_total_charge_current_battery') Or  IsNamedPolygon('48Vout2') Or  IsNamedPolygon('VBAT-') Or  IsNamedPolygon('CS-_total_charge_current_battery') Or  IsNamedPolygon('VBAT-') Or  IsNamedPolygon('48V2') Or  IsNamedPolygon('48Vout1') Or  IsNamedPolygon('5V') Or  IsNamedPolygon('48Vout2') Or  IsNamedPolygon('CS-_total_charge_current_battery') Or  IsNamedPolygon('5V') Or  IsNamedPolygon('CS-') Or  IsNamedPolygon('VBAT-') Or  IsNamedPolygon('5V') Or  IsNamedPolygon('VBAT-') Or  IsNamedPolygon('48Vout1') Or  IsNamedPolygon('CS-_total_discharge_current_bus') Or  IsNamedPolygon('48Vout1') Or  IsNamedPolygon('CS-') Or  IsNamedPolygon('5V') Or  IsNamedPolygon('48Vout2') Or  IsNamedPolygon('CS-_total_charge_current_battery') Or  IsNamedPolygon('48Vout1') Or  IsNamedPolygon('VBAT-') Or  IsNamedPolygon('48Vout2')] p5: connectstyle=Direct reliefconductorwidth=0.254 reliefentries=4 polygonreliefangle="90 Angle" airgapwidth=0.254
PolygonConnect PolygonConnect_27 [All vs IsNamedPolygon('VBAT-') Or  IsNamedPolygon('5V') Or  IsNamedPolygon('5V') Or  IsNamedPolygon('VBAT-') Or  IsNamedPolygon('VBAT-') Or  IsNamedPolygon('VBAT-') Or  IsNamedPolygon('VBAT-') Or  IsNamedPolygon('VBAT-') Or  IsNamedPolygon('CS-_total_discharge_current_bus') Or  IsNamedPolygon('48Vout1') Or  IsNamedPolygon('VBAT-') Or  IsNamedPolygon('VBAT-') Or  IsNamedPolygon('CS-_total_discharge_current_bus') Or  IsNamedPolygon('CS-_total_charge_current_battery') Or  IsNamedPolygon('CS-_total_discharge_current_bus') Or  IsNamedPolygon('5V') Or  IsNamedPolygon('VBAT-') Or  IsNamedPolygon('VBAT-') Or  IsNamedPolygon('5V') Or  IsNamedPolygon('VBAT-') Or  IsNamedPolygon('5V') Or  IsNamedPolygon('CS+_total_charge_current_battery') Or  IsNamedPolygon('VBAT-') Or  IsNamedPolygon('48Vout2') Or  IsNamedPolygon('CS-_total_charge_current_battery') Or  IsNamedPolygon('48Vout2') Or  IsNamedPolygon('48Vout2') Or  IsNamedPolygon('CS-') Or  IsNamedPolygon('VBAT-') Or  IsNamedPolygon('CS+_total_charge_current_battery') Or  IsNamedPolygon('CS-_total_discharge_current_bus') Or  IsNamedPolygon('5V') Or  IsNamedPolygon('CS-_total_charge_current_battery') Or  IsNamedPolygon('5V') Or  IsNamedPolygon('5V') Or  IsNamedPolygon('48Vout2') Or  IsNamedPolygon('48V2') Or  IsNamedPolygon('48VOUT1') Or  IsNamedPolygon('48Vout2') Or  IsNamedPolygon('48Vout2') Or  IsNamedPolygon('48Vout2') Or  IsNamedPolygon('CS-_total_discharge_current_bus') Or  IsNamedPolygon('5V') Or  IsNamedPolygon('CS-_total_discharge_current_bus') Or  IsNamedPolygon('48Vout1') Or  IsNamedPolygon('VBAT-') Or  IsNamedPolygon('CS-_total_charge_current_battery')] p6: connectstyle=Direct reliefconductorwidth=0.254 reliefentries=4 polygonreliefangle="90 Angle" airgapwidth=0.254
PolygonConnect PolygonConnect_26 [All vs IsNamedPolygon('48Vout2') Or  IsNamedPolygon('VBAT-') Or  IsNamedPolygon('VBAT-') Or  IsNamedPolygon('VBAT-') Or  IsNamedPolygon('5V') Or  IsNamedPolygon('CS-_total_discharge_current_bus') Or  IsNamedPolygon('CS-_total_charge_current_battery') Or  IsNamedPolygon('48Vout2') Or  IsNamedPolygon('48Vout1') Or  IsNamedPolygon('CS-_total_charge_current_battery') Or  IsNamedPolygon('5V') Or  IsNamedPolygon('CS+_total_charge_current_battery') Or  IsNamedPolygon('CS-_total_discharge_current_bus') Or  IsNamedPolygon('5V') Or  IsNamedPolygon('CS-_total_discharge_current_bus') Or  IsNamedPolygon('CS-_total_discharge_current_bus') Or  IsNamedPolygon('48Vout2') Or  IsNamedPolygon('VBAT-') Or  IsNamedPolygon('CS-_total_discharge_current_bus') Or  IsNamedPolygon('5V') Or  IsNamedPolygon('VBAT-') Or  IsNamedPolygon('5V') Or  IsNamedPolygon('VBAT-') Or  IsNamedPolygon('CS-_total_discharge_current_bus') Or  IsNamedPolygon('48Vout2') Or  IsNamedPolygon('48VOUT1') Or  IsNamedPolygon('48Vout1') Or  IsNamedPolygon('48Vout2') Or  IsNamedPolygon('5V') Or  IsNamedPolygon('VBAT-') Or  IsNamedPolygon('CS-_total_charge_current_battery') Or  IsNamedPolygon('48Vout2') Or  IsNamedPolygon('CS-') Or  IsNamedPolygon('VBAT-') Or  IsNamedPolygon('VBAT-') Or  IsNamedPolygon('5V') Or  IsNamedPolygon('5V') Or  IsNamedPolygon('48V2') Or  IsNamedPolygon('CS-_total_charge_current_battery') Or  IsNamedPolygon('VBAT-') Or  IsNamedPolygon('48Vout2') Or  IsNamedPolygon('CS+_total_charge_current_battery') Or  IsNamedPolygon('5V')] p7: connectstyle=Direct reliefconductorwidth=0.254 reliefentries=4 polygonreliefangle="90 Angle" airgapwidth=0.254
PolygonConnect PolygonConnect_25 [All vs IsNamedPolygon('CS-_total_discharge_current_bus') Or  IsNamedPolygon('VBAT-') Or  IsNamedPolygon('5V') Or  IsNamedPolygon('5V') Or  IsNamedPolygon('VBAT-') Or  IsNamedPolygon('CS-_total_charge_current_battery') Or  IsNamedPolygon('VBAT-') Or  IsNamedPolygon('5V') Or  IsNamedPolygon('CS-_total_discharge_current_bus') Or  IsNamedPolygon('5V') Or  IsNamedPolygon('CS-_total_charge_current_battery') Or  IsNamedPolygon('VBAT-') Or  IsNamedPolygon('CS-_total_discharge_current_bus') Or  IsNamedPolygon('48Vout2') Or  IsNamedPolygon('CS-_total_discharge_current_bus') Or  IsNamedPolygon('VBAT-') Or  IsNamedPolygon('VBAT-') Or  IsNamedPolygon('VBAT-') Or  IsNamedPolygon('CS-_total_discharge_current_bus') Or  IsNamedPolygon('48VOUT1') Or  IsNamedPolygon('CS+_total_charge_current_battery') Or  IsNamedPolygon('5V') Or  IsNamedPolygon('5V') Or  IsNamedPolygon('VBAT-') Or  IsNamedPolygon('48Vout2') Or  IsNamedPolygon('5V') Or  IsNamedPolygon('CS-_total_discharge_current_bus') Or  IsNamedPolygon('CS-_total_charge_current_battery') Or  IsNamedPolygon('48Vout2') Or  IsNamedPolygon('CS-_total_charge_current_battery') Or  IsNamedPolygon('48Vout2') Or  IsNamedPolygon('5V') Or  IsNamedPolygon('5V') Or  IsNamedPolygon('48Vout2') Or  IsNamedPolygon('CS+_total_charge_current_battery') Or  IsNamedPolygon('48V2') Or  IsNamedPolygon('VBAT-') Or  IsNamedPolygon('48Vout2')] p8: connectstyle=Direct reliefconductorwidth=0.254 reliefentries=4 polygonreliefangle="90 Angle" airgapwidth=0.254
PolygonConnect PolygonConnect_24 [All vs IsNamedPolygon('VBAT-') Or  IsNamedPolygon('VBAT-') Or  IsNamedPolygon('VBAT-') Or  IsNamedPolygon('48VOUT1') Or  IsNamedPolygon('VBAT-') Or  IsNamedPolygon('48VOUT2') Or  IsNamedPolygon('CS-_total_charge_current_battery') Or  IsNamedPolygon('VBAT-') Or  IsNamedPolygon('CS+_total_charge_current_battery') Or  IsNamedPolygon('VBAT-') Or  IsNamedPolygon('VBAT-') Or  IsNamedPolygon('VBAT-') Or  IsNamedPolygon('CS-_total_charge_current_battery') Or  IsNamedPolygon('VBAT-') Or  IsNamedPolygon('CS-_total_charge_current_battery') Or  IsNamedPolygon('48VOUT1') Or  IsNamedPolygon('AutoNaming') Or  IsNamedPolygon('VBAT-') Or  IsNamedPolygon('CS-_total_charge_current_battery') Or  IsNamedPolygon('48VOUT1') Or  IsNamedPolygon('VBAT-') Or  IsNamedPolygon('CS-_total_charge_current_battery') Or  IsNamedPolygon('48VOUT2') Or  IsNamedPolygon('48VOUT1') Or  IsNamedPolygon('12V') Or  IsNamedPolygon('VBAT-') Or  IsNamedPolygon('VBAT-') Or  IsNamedPolygon('CS+_total_charge_current_battery') Or  IsNamedPolygon('5V') Or  IsNamedPolygon('5V') Or  IsNamedPolygon('5V') Or  IsNamedPolygon('CS-_total_charge_current_battery') Or  IsNamedPolygon('CS-_total_charge_current_battery') Or  IsNamedPolygon('VBAT-') Or  IsNamedPolygon('VBAT-') Or  IsNamedPolygon('VBAT-') Or  IsNamedPolygon('5V') Or  IsNamedPolygon('VBAT-') Or  IsNamedPolygon('VBAT-') Or  IsNamedPolygon('48VOUT2') Or  IsNamedPolygon('VBAT-') Or  IsNamedPolygon('VBAT-') Or  IsNamedPolygon('VBAT-') Or  IsNamedPolygon('48VOUT1') Or  IsNamedPolygon('VBAT-') Or  IsNamedPolygon('CS+_total_charge_current_battery') Or  IsNamedPolygon('5V') Or  IsNamedPolygon('5V') Or  IsNamedPolygon('48Vout2') Or  IsNamedPolygon('CS-_total_charge_current_battery') Or  IsNamedPolygon('3V3') Or  IsNamedPolygon('CS-_total_discharge_current_bus') Or  IsNamedPolygon('CS-_total_discharge_current_bus') Or  IsNamedPolygon('CS-_total_discharge_current_bus') Or  IsNamedPolygon('CS-_total_discharge_current_bus') Or  IsNamedPolygon('CS-_total_discharge_current_bus') Or  IsNamedPolygon('48Vout2') Or  IsNamedPolygon('48Vout2') Or  IsNamedPolygon('5V') Or  IsNamedPolygon('12V') Or  IsNamedPolygon('48Vout2') Or  IsNamedPolygon('48Vout2') Or  IsNamedPolygon('48Vout2') Or  IsNamedPolygon('CS-_total_discharge_current_bus') Or  IsNamedPolygon('5V') Or  IsNamedPolygon('5V') Or  IsNamedPolygon('5V')] p9: connectstyle=Direct reliefconductorwidth=0.254 reliefentries=4 polygonreliefangle="90 Angle" airgapwidth=0.254
PolygonConnect PolygonConnect_23 [All vs IsNamedPolygon('5V') Or  IsNamedPolygon('12V') Or  IsNamedPolygon('CS+_total_charge_current_battery') Or  IsNamedPolygon('CS-_total_charge_current_battery') Or  IsNamedPolygon('5V') Or  IsNamedPolygon('VBAT-') Or  IsNamedPolygon('48VOUT1') Or  IsNamedPolygon('48VOUT1') Or  IsNamedPolygon('5V') Or  IsNamedPolygon('VBAT-') Or  IsNamedPolygon('VBAT-') Or  IsNamedPolygon('48Vout2') Or  IsNamedPolygon('VBAT-') Or  IsNamedPolygon('VBAT-') Or  IsNamedPolygon('48Vout2') Or  IsNamedPolygon('5V') Or  IsNamedPolygon('5V') Or  IsNamedPolygon('VBAT-') Or  IsNamedPolygon('CS-_total_discharge_current_bus') Or  IsNamedPolygon('VBAT-') Or  IsNamedPolygon('VBAT-') Or  IsNamedPolygon('48Vout2') Or  IsNamedPolygon('VBAT-') Or  IsNamedPolygon('CS-_total_charge_current_battery') Or  IsNamedPolygon('48VOUT2') Or  IsNamedPolygon('48Vout2') Or  IsNamedPolygon('CS-_total_discharge_current_bus') Or  IsNamedPolygon('VBAT-') Or  IsNamedPolygon('48Vout2') Or  IsNamedPolygon('CS-_total_charge_current_battery') Or  IsNamedPolygon('CS-_total_charge_current_battery') Or  IsNamedPolygon('5V') Or  IsNamedPolygon('48VOUT2') Or  IsNamedPolygon('CS-_total_charge_current_battery') Or  IsNamedPolygon('5V') Or  IsNamedPolygon('CS-_total_discharge_current_bus') Or  IsNamedPolygon('CS+_total_charge_current_battery') Or  IsNamedPolygon('CS-_total_discharge_current_bus') Or  IsNamedPolygon('48Vout2') Or  IsNamedPolygon('CS-_total_discharge_current_bus') Or  IsNamedPolygon('CS-_total_charge_current_battery') Or  IsNamedPolygon('5V') Or  IsNamedPolygon('CS-_total_discharge_current_bus') Or  IsNamedPolygon('VBAT-')] p10: connectstyle=Direct reliefconductorwidth=0.254 reliefentries=4 polygonreliefangle="90 Angle" airgapwidth=0.254
PolygonConnect PolygonConnect_22 [All vs IsNamedPolygon('5V') Or  IsNamedPolygon('VBAT-') Or  IsNamedPolygon('CS-_total_discharge_current_bus') Or  IsNamedPolygon('CS-_total_discharge_current_bus') Or  IsNamedPolygon('5V') Or  IsNamedPolygon('CS-_total_discharge_current_bus') Or  IsNamedPolygon('VBAT-') Or  IsNamedPolygon('48Vout2') Or  IsNamedPolygon('48Vout2') Or  IsNamedPolygon('48Vout2') Or  IsNamedPolygon('48VOUT2') Or  IsNamedPolygon('CS-_total_discharge_current_bus') Or  IsNamedPolygon('CS-_total_charge_current_battery') Or  IsNamedPolygon('48Vout2') Or  IsNamedPolygon('CS+_total_charge_current_battery') Or  IsNamedPolygon('12V') Or  IsNamedPolygon('CS-_total_discharge_current_bus') Or  IsNamedPolygon('48Vout2') Or  IsNamedPolygon('CS-_total_charge_current_battery') Or  IsNamedPolygon('48Vout2') Or  IsNamedPolygon('CS-_total_discharge_current_bus') Or  IsNamedPolygon('VBAT-') Or  IsNamedPolygon('48VOUT2') Or  IsNamedPolygon('48VOUT1') Or  IsNamedPolygon('VBAT-')] p11: connectstyle=Direct reliefconductorwidth=0.254 reliefentries=4 polygonreliefangle="90 Angle" airgapwidth=0.254
PolygonConnect PolygonConnect_21 [All vs IsNamedPolygon('CS+_total_charge_current_battery') Or  IsNamedPolygon('CS-_total_discharge_current_bus') Or  IsNamedPolygon('48Vout2') Or  IsNamedPolygon('CS-_total_discharge_current_bus') Or  IsNamedPolygon('48Vout2') Or  IsNamedPolygon('CS-_total_discharge_current_bus') Or  IsNamedPolygon('12V') Or  IsNamedPolygon('CS-_total_discharge_current_bus') Or  IsNamedPolygon('5V') Or  IsNamedPolygon('48Vout2') Or  IsNamedPolygon('48Vout2') Or  IsNamedPolygon('CS-_total_discharge_current_bus') Or  IsNamedPolygon('CS-_total_charge_current_battery') Or  IsNamedPolygon('5V') Or  IsNamedPolygon('48Vout2') Or  IsNamedPolygon('VBAT-') Or  IsNamedPolygon('48Vout2') Or  IsNamedPolygon('CS-_total_discharge_current_bus')] p12: connectstyle=Direct reliefconductorwidth=0.254 reliefentries=4 polygonreliefangle="90 Angle" airgapwidth=0.254
PolygonConnect PolygonConnect_20 [All vs IsNamedPolygon('48Vout2') Or  IsNamedPolygon('CS+_total_charge_current_battery') Or  IsNamedPolygon('48Vout2') Or  IsNamedPolygon('5V') Or  IsNamedPolygon('12V') Or  IsNamedPolygon('48Vout2') Or  IsNamedPolygon('48Vout2') Or  IsNamedPolygon('48Vout2') Or  IsNamedPolygon('48Vout2') Or  IsNamedPolygon('CS-_total_charge_current_battery') Or  IsNamedPolygon('VBAT-') Or  IsNamedPolygon('5V')] p13: connectstyle=Direct reliefconductorwidth=0.254 reliefentries=4 polygonreliefangle="90 Angle" airgapwidth=0.254
PolygonConnect PolygonConnect_19 [All vs IsNamedPolygon('VBAT-') Or  IsNamedPolygon('VBAT-') Or  IsNamedPolygon('VBAT-') Or  IsNamedPolygon('SW2') Or  IsNamedPolygon('VBAT_DISCH_IN') Or  IsNamedPolygon('VBAT_DISCH_IN') Or  IsNamedPolygon('VBAT_DISCH_IN') Or  IsNamedPolygon('CSB_DISCH') Or  IsNamedPolygon('VBAT-') Or  IsNamedPolygon('5V') Or  IsNamedPolygon('VBAT-') Or  IsNamedPolygon('SNGD') Or  IsNamedPolygon('VBAT-') Or  IsNamedPolygon('VBAT-') Or  IsNamedPolygon('SW2') Or  IsNamedPolygon('VBAT-') Or  IsNamedPolygon('VBAT-') Or  IsNamedPolygon('CSA_DISCH') Or  IsNamedPolygon('48V_DISCH_OUT') Or  IsNamedPolygon('VBAT_DISCH_IN') Or  IsNamedPolygon('VBAT-') Or  IsNamedPolygon('VBAT-') Or  IsNamedPolygon('48V_DISCH_OUT') Or  IsNamedPolygon('VBAT-') Or  IsNamedPolygon('CSA_DISCH') Or  IsNamedPolygon('5V') Or  IsNamedPolygon('VBAT-') Or  IsNamedPolygon('VBAT-') Or  IsNamedPolygon('48V_DISCH_OUT') Or  IsNamedPolygon('48V_DISCH_OUT') Or  IsNamedPolygon('VBAT-') Or  IsNamedPolygon('12V_AUX') Or  IsNamedPolygon('48V_DISCH_OUT') Or  IsNamedPolygon('VBAT_DISCH_IN') Or  IsNamedPolygon('VBAT_DISCH_IN') Or  IsNamedPolygon('VBAT-')] p14: connectstyle=Direct reliefconductorwidth=0.254 reliefentries=4 polygonreliefangle="90 Angle" airgapwidth=0.254
PolygonConnect PolygonConnect_18 [All vs IsNamedPolygon('SW2') Or  IsNamedPolygon('VBAT_DISCH_IN') Or  IsNamedPolygon('VBAT_DISCH_IN') Or  IsNamedPolygon('VBAT_DISCH_IN') Or  IsNamedPolygon('48V_DISCH_OUT') Or  IsNamedPolygon('VBAT_DISCH_IN') Or  IsNamedPolygon('VBAT-') Or  IsNamedPolygon('VBAT-') Or  IsNamedPolygon('VBAT-') Or  IsNamedPolygon('VBAT-') Or  IsNamedPolygon('VBAT-') Or  IsNamedPolygon('VBAT_DISCH_IN') Or  IsNamedPolygon('VBAT-') Or  IsNamedPolygon('CSA_DISCH') Or  IsNamedPolygon('VBAT-') Or  IsNamedPolygon('48V_DISCH_OUT') Or  IsNamedPolygon('48V_DISCH_OUT') Or  IsNamedPolygon('5V') Or  IsNamedPolygon('VBAT-') Or  IsNamedPolygon('VBAT-') Or  IsNamedPolygon('VBAT-') Or  IsNamedPolygon('VBAT-') Or  IsNamedPolygon('12V_AUX') Or  IsNamedPolygon('CSA_DISCH') Or  IsNamedPolygon('CSB_DISCH') Or  IsNamedPolygon('VBAT-') Or  IsNamedPolygon('VBAT-') Or  IsNamedPolygon('VBAT_DISCH_IN')] p15: connectstyle=Direct reliefconductorwidth=0.254 reliefentries=4 polygonreliefangle="90 Angle" airgapwidth=0.254
PolygonConnect PolygonConnect_17 [All vs IsNamedPolygon('VBAT-') Or  IsNamedPolygon('VBAT_DISCH_IN') Or  IsNamedPolygon('VBAT-') Or  IsNamedPolygon('VBAT_DISCH_IN') Or  IsNamedPolygon('CSA_DISCH') Or  IsNamedPolygon('VBAT_DISCH_IN') Or  IsNamedPolygon('VBAT_DISCH_IN') Or  IsNamedPolygon('VBAT-') Or  IsNamedPolygon('VBAT-') Or  IsNamedPolygon('48V_DISCH_OUT') Or  IsNamedPolygon('CSA_DISCH') Or  IsNamedPolygon('VBAT-') Or  IsNamedPolygon('VBAT_DISCH_IN') Or  IsNamedPolygon('VBAT-') Or  IsNamedPolygon('5V') Or  IsNamedPolygon('48V_DISCH_OUT') Or  IsNamedPolygon('VBAT-') Or  IsNamedPolygon('CSB_DISCH') Or  IsNamedPolygon('SW2') Or  IsNamedPolygon('VBAT-') Or  IsNamedPolygon('48V_DISCH_OUT') Or  IsNamedPolygon('VBAT-') Or  IsNamedPolygon('VBAT_DISCH_IN')] p16: connectstyle=Direct reliefconductorwidth=0.254 reliefentries=4 polygonreliefangle="90 Angle" airgapwidth=0.254
PolygonConnect PolygonConnect_16 [All vs IsNamedPolygon('VBAT-') Or  IsNamedPolygon('VBAT-') Or  IsNamedPolygon('CSA_DISCH') Or  IsNamedPolygon('48V_DISCH_OUT') Or  IsNamedPolygon('VBAT_DISCH_IN') Or  IsNamedPolygon('VBAT-') Or  IsNamedPolygon('VBAT-') Or  IsNamedPolygon('VBAT-') Or  IsNamedPolygon('VBAT-') Or  IsNamedPolygon('VBAT_DISCH_IN') Or  IsNamedPolygon('VBAT_DISCH_IN') Or  IsNamedPolygon('CSB_DISCH') Or  IsNamedPolygon('VBAT-') Or  IsNamedPolygon('VBAT_DISCH_IN') Or  IsNamedPolygon('VBAT_DISCH_IN') Or  IsNamedPolygon('VBAT-') Or  IsNamedPolygon('VBAT_DISCH_IN') Or  IsNamedPolygon('SW2') Or  IsNamedPolygon('CSA_DISCH') Or  IsNamedPolygon('VBAT-')] p17: connectstyle=Direct reliefconductorwidth=0.254 reliefentries=4 polygonreliefangle="90 Angle" airgapwidth=0.254
PolygonConnect PolygonConnect_15 [All vs IsNamedPolygon('CSA_DISCH') Or  IsNamedPolygon('VBAT-') Or  IsNamedPolygon('VBAT-') Or  IsNamedPolygon('48V_DISCH_OUT') Or  IsNamedPolygon('VBAT_DISCH_IN') Or  IsNamedPolygon('SW2') Or  IsNamedPolygon('VBAT_DISCH_IN') Or  IsNamedPolygon('VBAT-') Or  IsNamedPolygon('VBAT_DISCH_IN') Or  IsNamedPolygon('CSB_DISCH') Or  IsNamedPolygon('VBAT_DISCH_IN') Or  IsNamedPolygon('CSA_DISCH') Or  IsNamedPolygon('VBAT_DISCH_IN')] p18: connectstyle=Direct reliefconductorwidth=0.254 reliefentries=4 polygonreliefangle="90 Angle" airgapwidth=0.254
PolygonConnect PolygonConnect_14 [All vs IsNamedPolygon('SW2') Or  IsNamedPolygon('48V_DISCH_OUT') Or  IsNamedPolygon('VBAT-') Or  IsNamedPolygon('VBAT-') Or  IsNamedPolygon('CSA_DISCH') Or  IsNamedPolygon('CSB_DISCH')] p19: connectstyle=Direct reliefconductorwidth=0.254 reliefentries=4 polygonreliefangle="90 Angle" airgapwidth=0.254
PolygonConnect PolygonConnect_13 [All vs IsNamedPolygon('VBAT-') Or  IsNamedPolygon('48V_DISCH_OUT') Or  IsNamedPolygon('VBAT-') Or  IsNamedPolygon('CSB_DISCH') Or  IsNamedPolygon('CSA_DISCH')] p20: connectstyle=Direct reliefconductorwidth=0.254 reliefentries=4 polygonreliefangle="90 Angle" airgapwidth=0.254
PolygonConnect PolygonConnect_12 [All vs IsNamedPolygon('48V_DISCH_OUT') Or  IsNamedPolygon('VBAT-') Or  IsNamedPolygon('VBAT-')] p21: connectstyle=Direct reliefconductorwidth=0.254 reliefentries=4 polygonreliefangle="90 Angle" airgapwidth=0.254
PolygonConnect PolygonConnect_11 [All vs IsNamedPolygon('GND') Or  IsNamedPolygon('D101_2') Or  IsNamedPolygon('V+') Or  IsNamedPolygon('GND') Or  IsNamedPolygon('C128_1') Or  IsNamedPolygon('J2_2') Or  IsNamedPolygon('CS') Or  IsNamedPolygon('V+') Or  IsNamedPolygon('GND') Or  IsNamedPolygon('J2_2') Or  IsNamedPolygon('PGND') Or  IsNamedPolygon('12V') Or  IsNamedPolygon('PGND') Or  IsNamedPolygon('PGND') Or  IsNamedPolygon('V+') Or  IsNamedPolygon('V+') Or  IsNamedPolygon('D101_2') Or  IsNamedPolygon('CS') Or  IsNamedPolygon('GND')] p22: connectstyle=Direct reliefconductorwidth=0.254 reliefentries=4 polygonreliefangle="90 Angle" airgapwidth=0.254
PolygonConnect PolygonConnect_10 [All vs IsNamedPolygon('GND') Or  IsNamedPolygon('C128_1') Or  IsNamedPolygon('GND') Or  IsNamedPolygon('J2_2') Or  IsNamedPolygon('GND') Or  IsNamedPolygon('D101_2') Or  IsNamedPolygon('J2_2') Or  IsNamedPolygon('V+') Or  IsNamedPolygon('PGND') Or  IsNamedPolygon('CS') Or  IsNamedPolygon('V+')] p23: connectstyle=Direct reliefconductorwidth=0.254 reliefentries=4 polygonreliefangle="90 Angle" airgapwidth=0.254
PolygonConnect PolygonConnect_9 [All vs IsNamedPolygon('J2_2') Or  IsNamedPolygon('GND') Or  IsNamedPolygon('8V5') Or  IsNamedPolygon('V+') Or  IsNamedPolygon('R117_1') Or  IsNamedPolygon('PGND') Or  IsNamedPolygon('PGND') Or  IsNamedPolygon('Drv') Or  IsNamedPolygon('V+') Or  IsNamedPolygon('V+') Or  IsNamedPolygon('C128_1') Or  IsNamedPolygon('GND') Or  IsNamedPolygon('GND') Or  IsNamedPolygon('J2_2') Or  IsNamedPolygon('PGND')] p24: connectstyle=Direct reliefconductorwidth=0.254 reliefentries=4 polygonreliefangle="90 Angle" airgapwidth=0.254
PolygonConnect PolygonConnect_8 [All vs IsNamedPolygon('8V5') Or  IsNamedPolygon('J2_2') Or  IsNamedPolygon('PGND') Or  IsNamedPolygon('GND') Or  IsNamedPolygon('GND') Or  IsNamedPolygon('V+') Or  IsNamedPolygon('J2_2') Or  IsNamedPolygon('V+') Or  IsNamedPolygon('C128_1') Or  IsNamedPolygon('V+') Or  IsNamedPolygon('PGND') Or  IsNamedPolygon('J2_2') Or  IsNamedPolygon('J2_2') Or  IsNamedPolygon('R117_1')] p25: connectstyle=Direct reliefconductorwidth=0.254 reliefentries=4 polygonreliefangle="90 Angle" airgapwidth=0.254
PolygonConnect PolygonConnect_7 [All vs IsNamedPolygon('J2_2') Or  IsNamedPolygon('J2_2') Or  IsNamedPolygon('J2_2') Or  IsNamedPolygon('C128_1') Or  IsNamedPolygon('J2_2')] p26: connectstyle=Direct reliefconductorwidth=0.254 reliefentries=4 polygonreliefangle="90 Angle" airgapwidth=0.254
PolygonConnect PolygonConnect_6 [All vs IsNamedPolygon('J2_2')] p27: connectstyle=Direct reliefconductorwidth=0.254 reliefentries=4 polygonreliefangle="90 Angle" airgapwidth=0.254
PolygonConnect PolygonConnect_5 [All vs IsNamedPolygon('GND') Or  IsNamedPolygon('Vout') Or  IsNamedPolygon('Bottom Layer-SW') Or  IsNamedPolygon('GND') Or  IsNamedPolygon('C1_1') Or  IsNamedPolygon('Q1_3') Or  IsNamedPolygon('J2_2') Or  IsNamedPolygon('GND') Or  IsNamedPolygon('J2_2') Or  IsNamedPolygon('GND') Or  IsNamedPolygon('Vout') Or  IsNamedPolygon('Top Layer-SW') Or  IsNamedPolygon('Q1_3') Or  IsNamedPolygon('GND') Or  IsNamedPolygon('J2_2') Or  IsNamedPolygon('J2_2') Or  IsNamedPolygon('GND') Or  IsNamedPolygon('GND') Or  IsNamedPolygon('GND') Or  IsNamedPolygon('GND') Or  IsNamedPolygon('GND')] p28: connectstyle=Direct reliefconductorwidth=0.254 reliefentries=4 polygonreliefangle="90 Angle" airgapwidth=0.254
PolygonConnect PolygonConnect_4 [All vs IsNamedPolygon('GND') Or  IsNamedPolygon('Bottom Layer-SW') Or  IsNamedPolygon('C1_1') Or  IsNamedPolygon('Top Layer-SW') Or  IsNamedPolygon('GND') Or  IsNamedPolygon('GND') Or  IsNamedPolygon('GND') Or  IsNamedPolygon('Q1_3') Or  IsNamedPolygon('Vout') Or  IsNamedPolygon('Q1_3') Or  IsNamedPolygon('Vout')] p29: connectstyle=Direct reliefconductorwidth=0.254 reliefentries=4 polygonreliefangle="90 Angle" airgapwidth=0.254
PolygonConnect PolygonConnect_3 [All vs IsNamedPolygon('Q1_3') Or  IsNamedPolygon('Q1_3') Or  IsNamedPolygon('Top Layer-SW') Or  IsNamedPolygon('C1_1') Or  IsNamedPolygon('Bottom Layer-SW')] p30: connectstyle=Direct reliefconductorwidth=0.254 reliefentries=4 polygonreliefangle="90 Angle" airgapwidth=0.254
PolygonConnect PolygonConnect_2 [All vs IsNamedPolygon('Top Layer-SW') Or  IsNamedPolygon('Bottom Layer-SW')] p31: connectstyle=Direct reliefconductorwidth=0.254 reliefentries=4 polygonreliefangle="90 Angle" airgapwidth=0.254
PolygonConnect PolygonConnect_1 [All vs IsNamedPolygon('Bottom Layer-SW') Or  IsNamedPolygon('Top Layer-SW')] p32: thpad.connectstyle=Direct thpad.reliefconductorwidth=0.254 thpad.reliefentries=4 thpad.polygonreliefangle="90 Angle" thpad.airgapwidth=0.254 smdpad.connectstyle=Direct smdpad.reliefconductorwidth=0.254 smdpad.reliefentries=4 smdpad.polygonreliefangle="90 Angle" smdpad.airgapwidth=0.254 via.connectstyle=Relief via.reliefconductorwidth=0.254 via.reliefentries=4 via.polygonreliefangle="90 Angle" via.airgapwidth=0.254
PolygonConnect [All] p33: connectstyle=Direct reliefconductorwidth=0.254 reliefentries=4 polygonreliefangle="90 Angle" airgapwidth=0.254
RoutingVias ThermalPadVias [IsVia and InAnyComponent] p1: holewidth=0.2 width=0.5 viastyle="Through Hole" minholewidth=0.2 minwidth=0.5 maxholewidth=0.635 maxwidth=0.914
RoutingVias [All] p2: holewidth=0.254 width=0.508 viastyle="Through Hole" minholewidth=0.2 minwidth=0.508 maxholewidth=1.016 maxwidth=1.651
SilkToBoardRegionClearance [Not ((IsComment or IsDesignator) And (Hide <> 'False')) and not InRegion(1000,500,4000,800)] p1:
SilkToSilkClearance SilkToSilkClearance_Pb-FreeLogo [(HasFootprint('Pb-Free_Overlay_Medium') OR HasFootprint('Pb-Free_Overlay_Small')) vs (HasFootprint('Pb-Free_Overlay_Medium') OR HasFootprint('Pb-Free_Overlay_Small'))] p1: silktosilkclearance=0
SilkToSilkClearance [All] p2: silktosilkclearance=0.102
SilkToSolderMaskClearance SilkToComponentPadClearance [(IsPad or IsFill or IsRegion) and InAnycomponent] p1: minsilkscreentomaskgap=0.127 clearancetoexposedcopper=TRUE
SilkToSolderMaskClearance "Silk to Solder Mask Opening" [All] p2: minsilkscreentomaskgap=0.102 clearancetoexposedcopper=FALSE
SolderMaskExpansion [All] p1: expansion=0.05 istentingtop=FALSE
SupplyNets "Schematic Supply Nets" [InNet('VBAT-')] p1: voltage=0.000
SupplyNets "Schematic Supply Nets_1" [InNet('SGND')] p2: voltage=0.000
Width [All] p1: maxlimit=5 minlimit=0.2 preferedwidth=0.3 checkconnectedcopper=TRUE
14 further rules are at their usual default settings.

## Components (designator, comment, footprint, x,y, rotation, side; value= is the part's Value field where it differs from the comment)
C701 "A769MS107M1JLAS018" FP-A769MS107M1JLAS018_RADIAL-MFG 53.9,19.4 r0 bottom value=100µF
C702 "A769MS107M1JLAS018" FP-A769MS107M1JLAS018_RADIAL-MFG 53.9,30.3 r0 bottom value=100µF
C703 "A769MS107M1JLAS018" FP-A769MS107M1JLAS018_RADIAL-MFG 38.5,30.3 r180 bottom value=100µF
C704 "A769MS107M1JLAS018" FP-A769MS107M1JLAS018_RADIAL-MFG 38.5,19.4 r180 bottom value=100µF
R700 "PU3921FKNP90U4L" FP-PU3921FKNP90U4L_3921-MFG 17.6,65 r90 top value=400µ
R701 "PU3921FKNP90U4L" FP-PU3921FKNP90U4L_3921-MFG 36.3,65 r90 top value=400µ
R702 "PU3921FKNP90U4L" FP-PU3921FKNP90U4L_3921-MFG 30.1,65 r90 top value=400µ
R703 "PU3921FKNP90U4L" FP-PU3921FKNP90U4L_3921-MFG 23.841,65.003 r90 top value=400µ
R704 "PU3921FKNP90U4L" FP-PU3921FKNP90U4L_3921-MFG 42.5,65 r90 top value=400µ
R705 "PU3921FKNP90U4L" FP-PU3921FKNP90U4L_3921-MFG 48.7,65 r90 top value=400µ
R706 "PU3921FKNP90U4L" FP-PU3921FKNP90U4L_3921-MFG 54.9,65 r90 top value=400µ
R707 "PU3921FKNP90U4L" FP-PU3921FKNP90U4L_3921-MFG 61.1,65 r90 top value=400µ
T300 "CB70-14-CY" CB70-14-CY 26.5,140.3 r270 bottom
T301 "CB70-14-CY" CB70-14-CY 46.5,140.3 r270 bottom

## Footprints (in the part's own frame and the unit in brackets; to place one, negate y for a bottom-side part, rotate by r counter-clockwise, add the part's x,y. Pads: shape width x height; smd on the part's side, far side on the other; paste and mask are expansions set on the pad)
CB70-14-CY [mil] "Terminal 90A Lug"
  rect 680x500 hole 254 copper offset -90,0 paste-99999: 1(0,0)
  body extent -1300,-260 250,260, height 714
FP-A769MS107M1JLAS018_RADIAL-MFG [mm]
  rrect5% 4.4x2.2 smd paste+0 mask+0: 1(-4.45,0) 2(4.45,0)
  silkscreen extent -7.4,-5.25 5.25,5.25, body extent -5.5,-5.15 5.5,5.15, height 10.71
FP-PU3921FKNP90U4L_3921-MFG [mm]
  rrect4% 2.75x6.2 smd paste+0 mask+0: 1(-4.175,0) 2(4.175,0)
  silkscreen extent -2.42,-2.73 2.42,2.73, body extent -5,-2.6 5,2.6, height 1.81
